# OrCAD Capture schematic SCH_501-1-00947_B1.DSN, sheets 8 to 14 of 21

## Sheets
8 P08_CPU SIGNAL 2: size A2
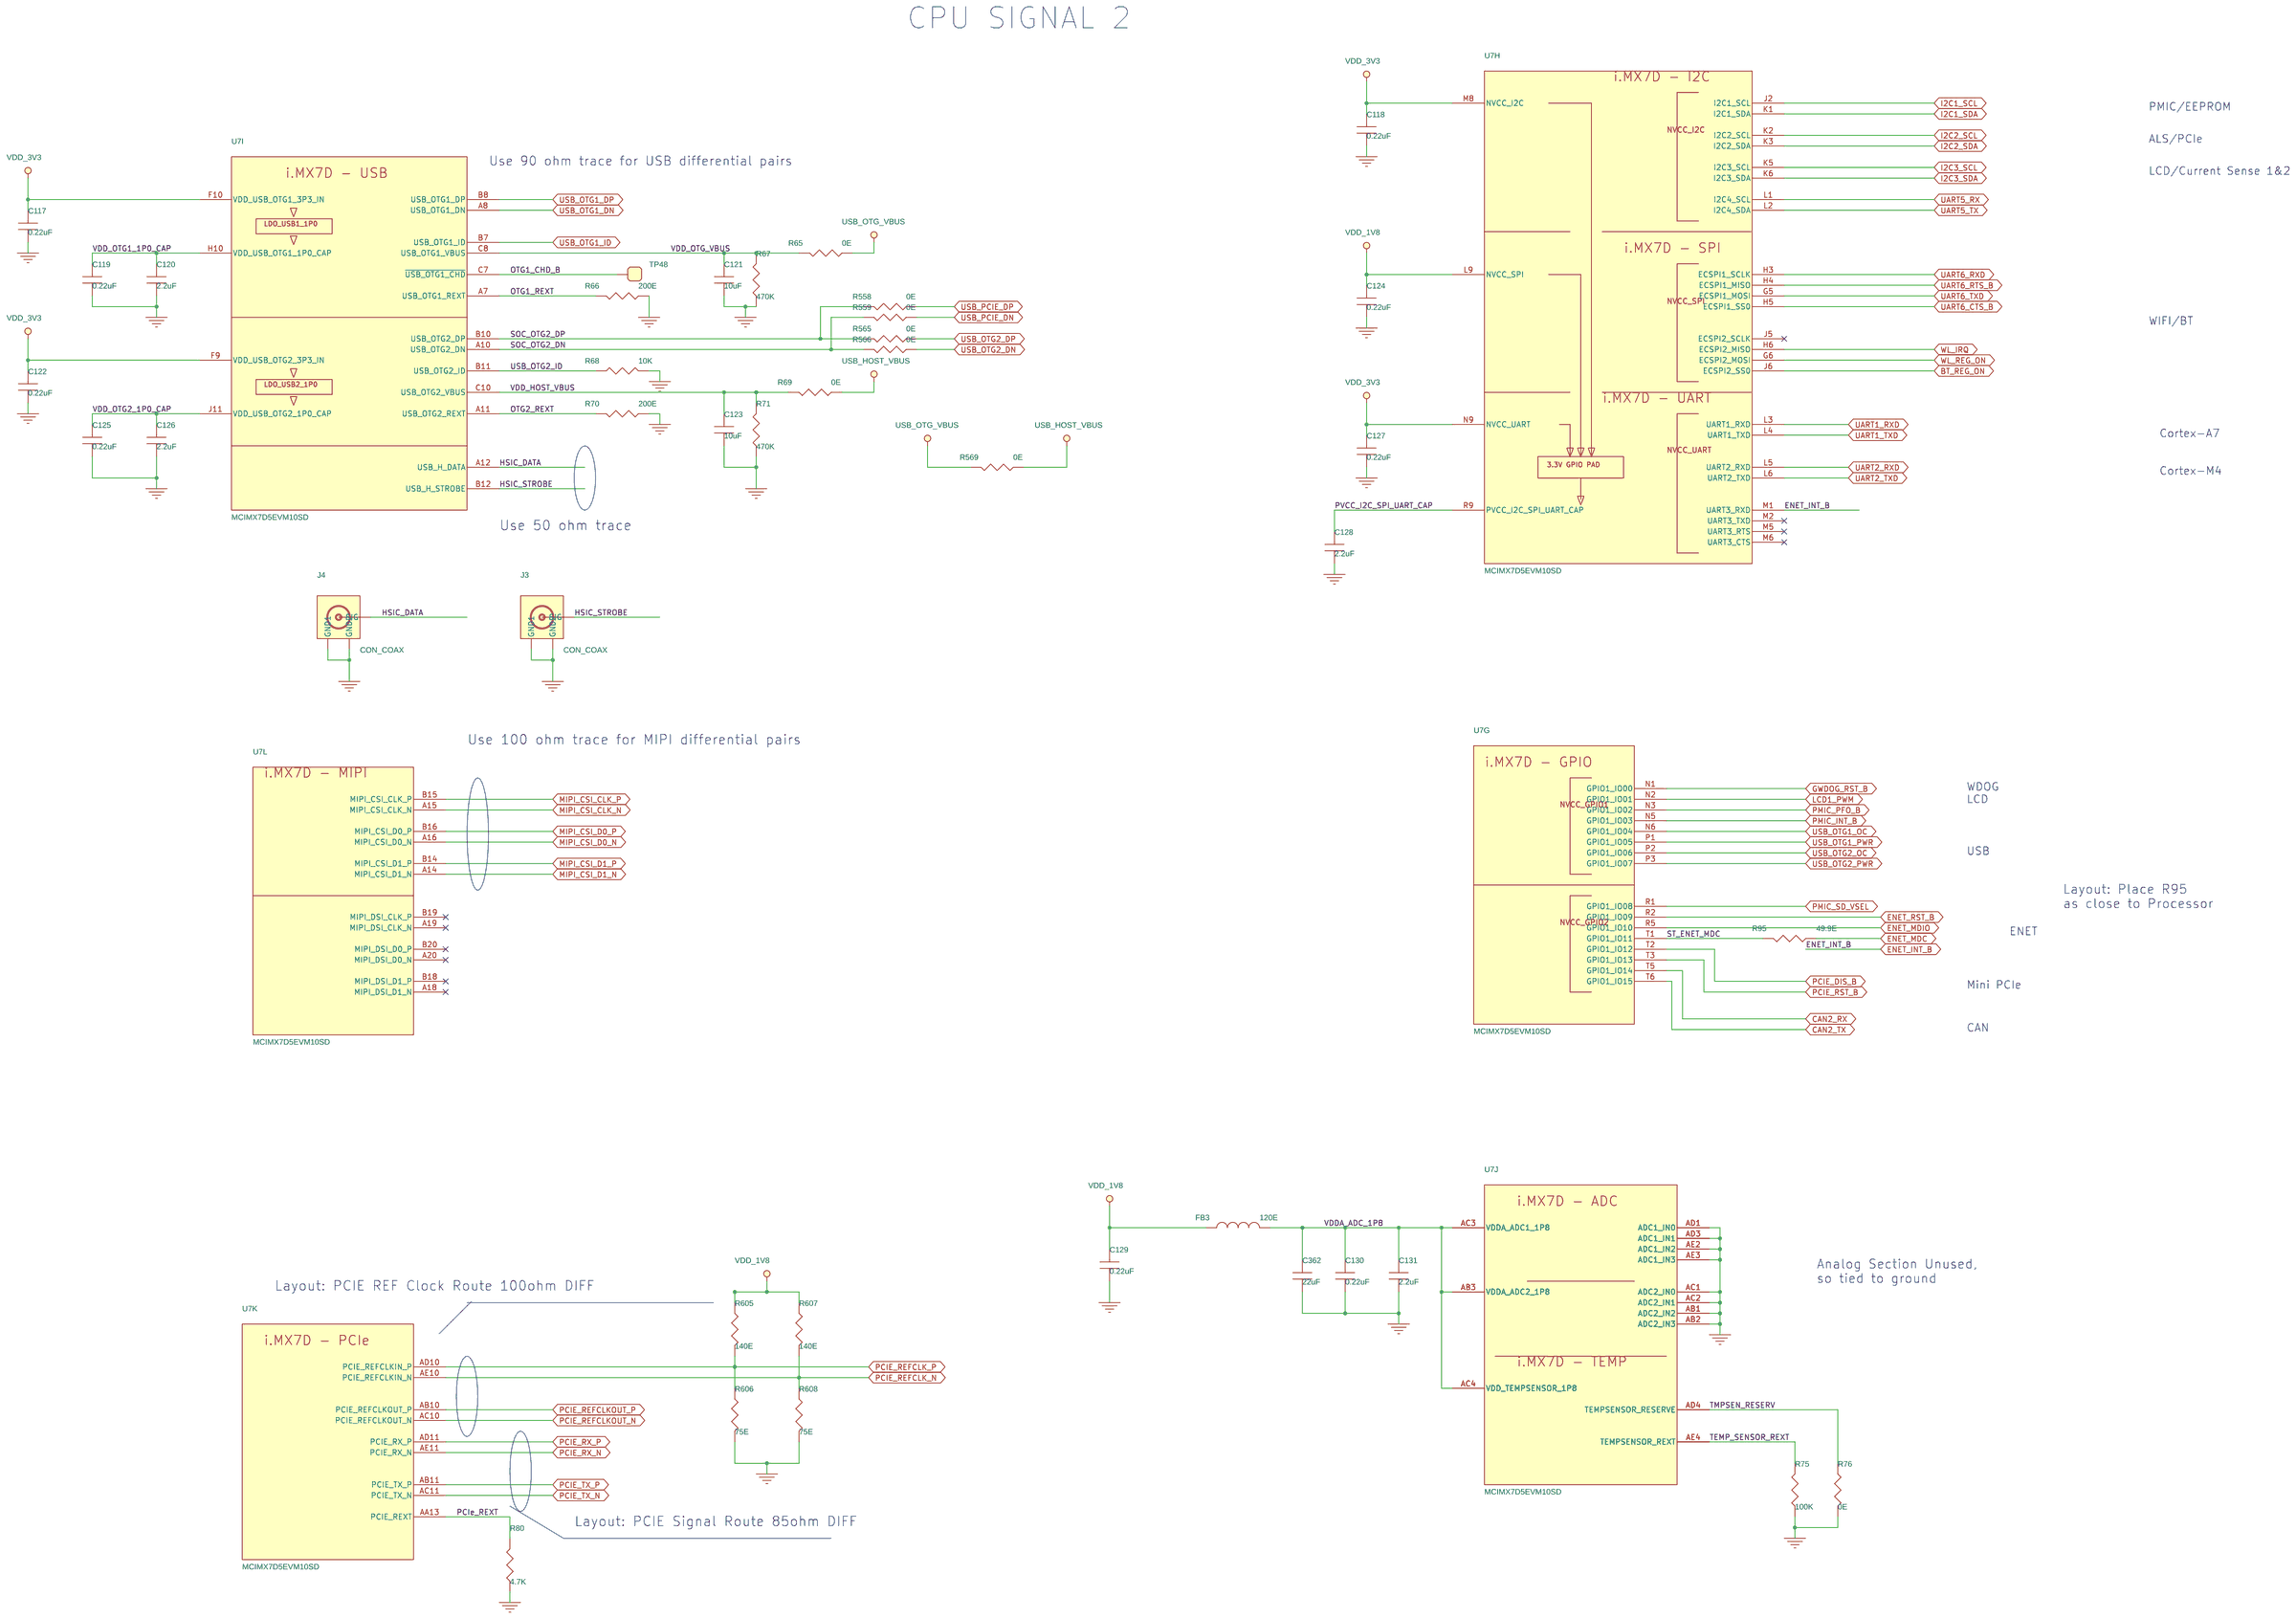
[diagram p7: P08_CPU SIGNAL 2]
9 P09_DDR3L: size A2
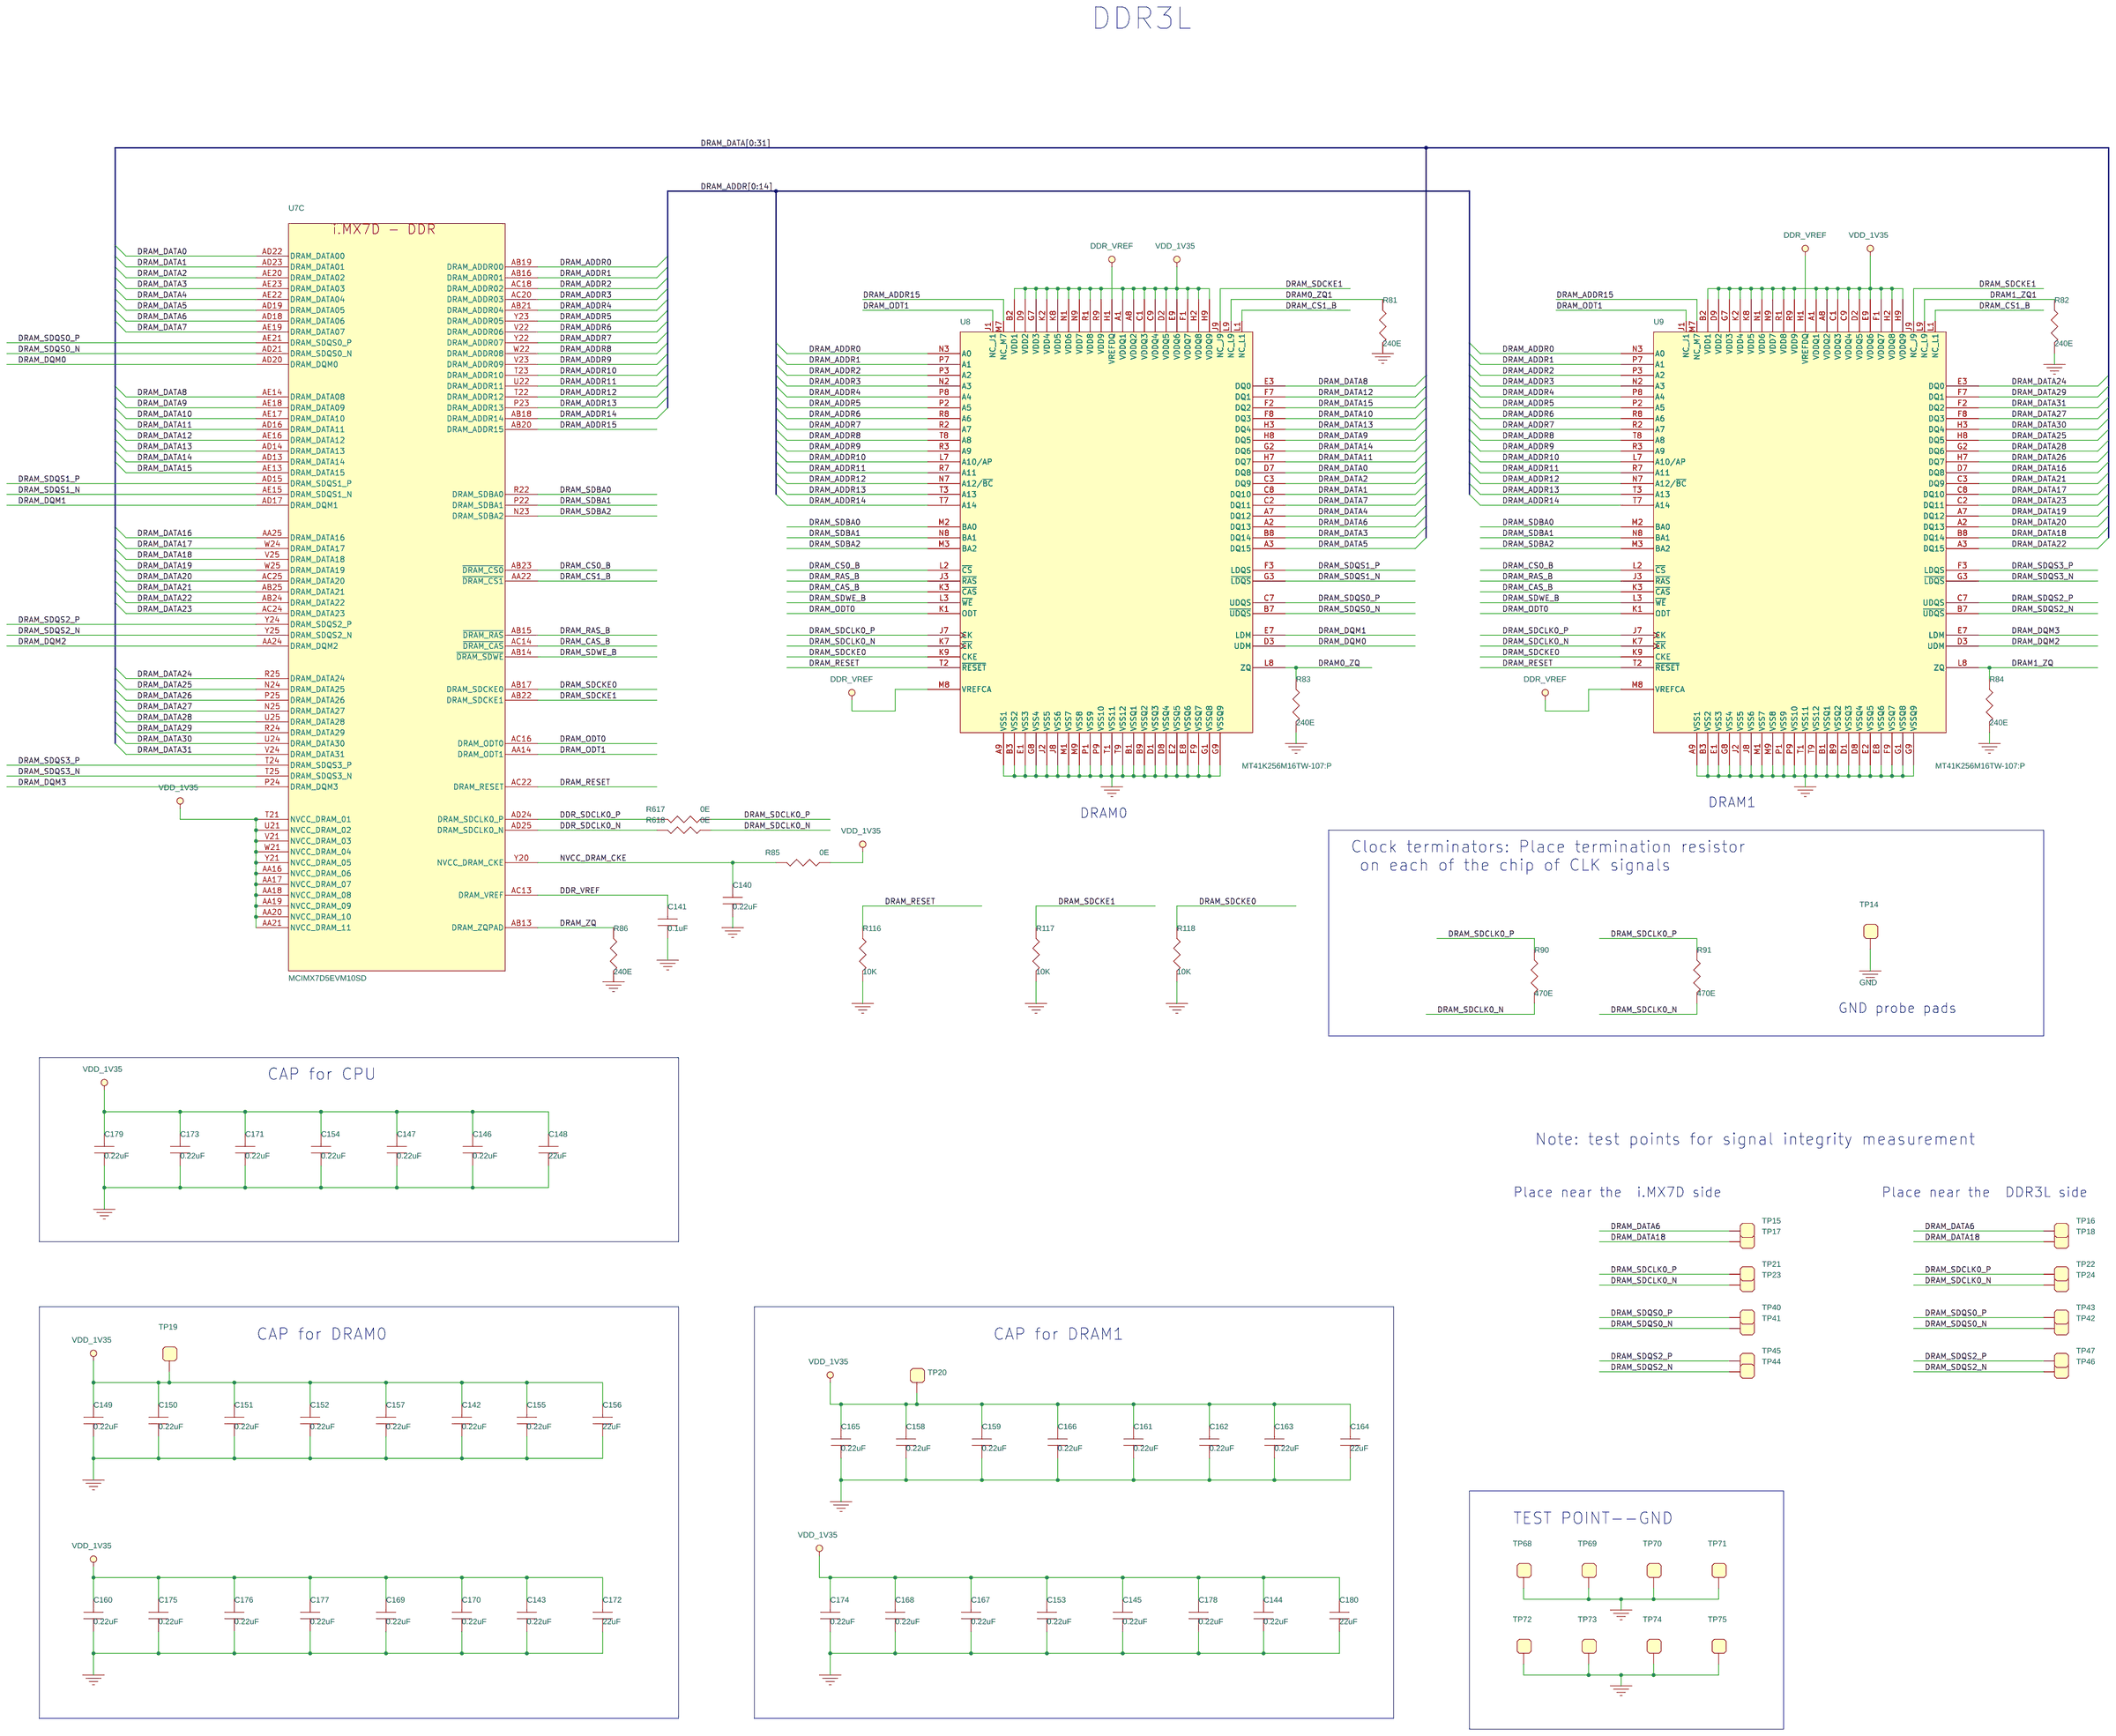
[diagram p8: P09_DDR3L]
10 P11_mini_PCIe: size A2
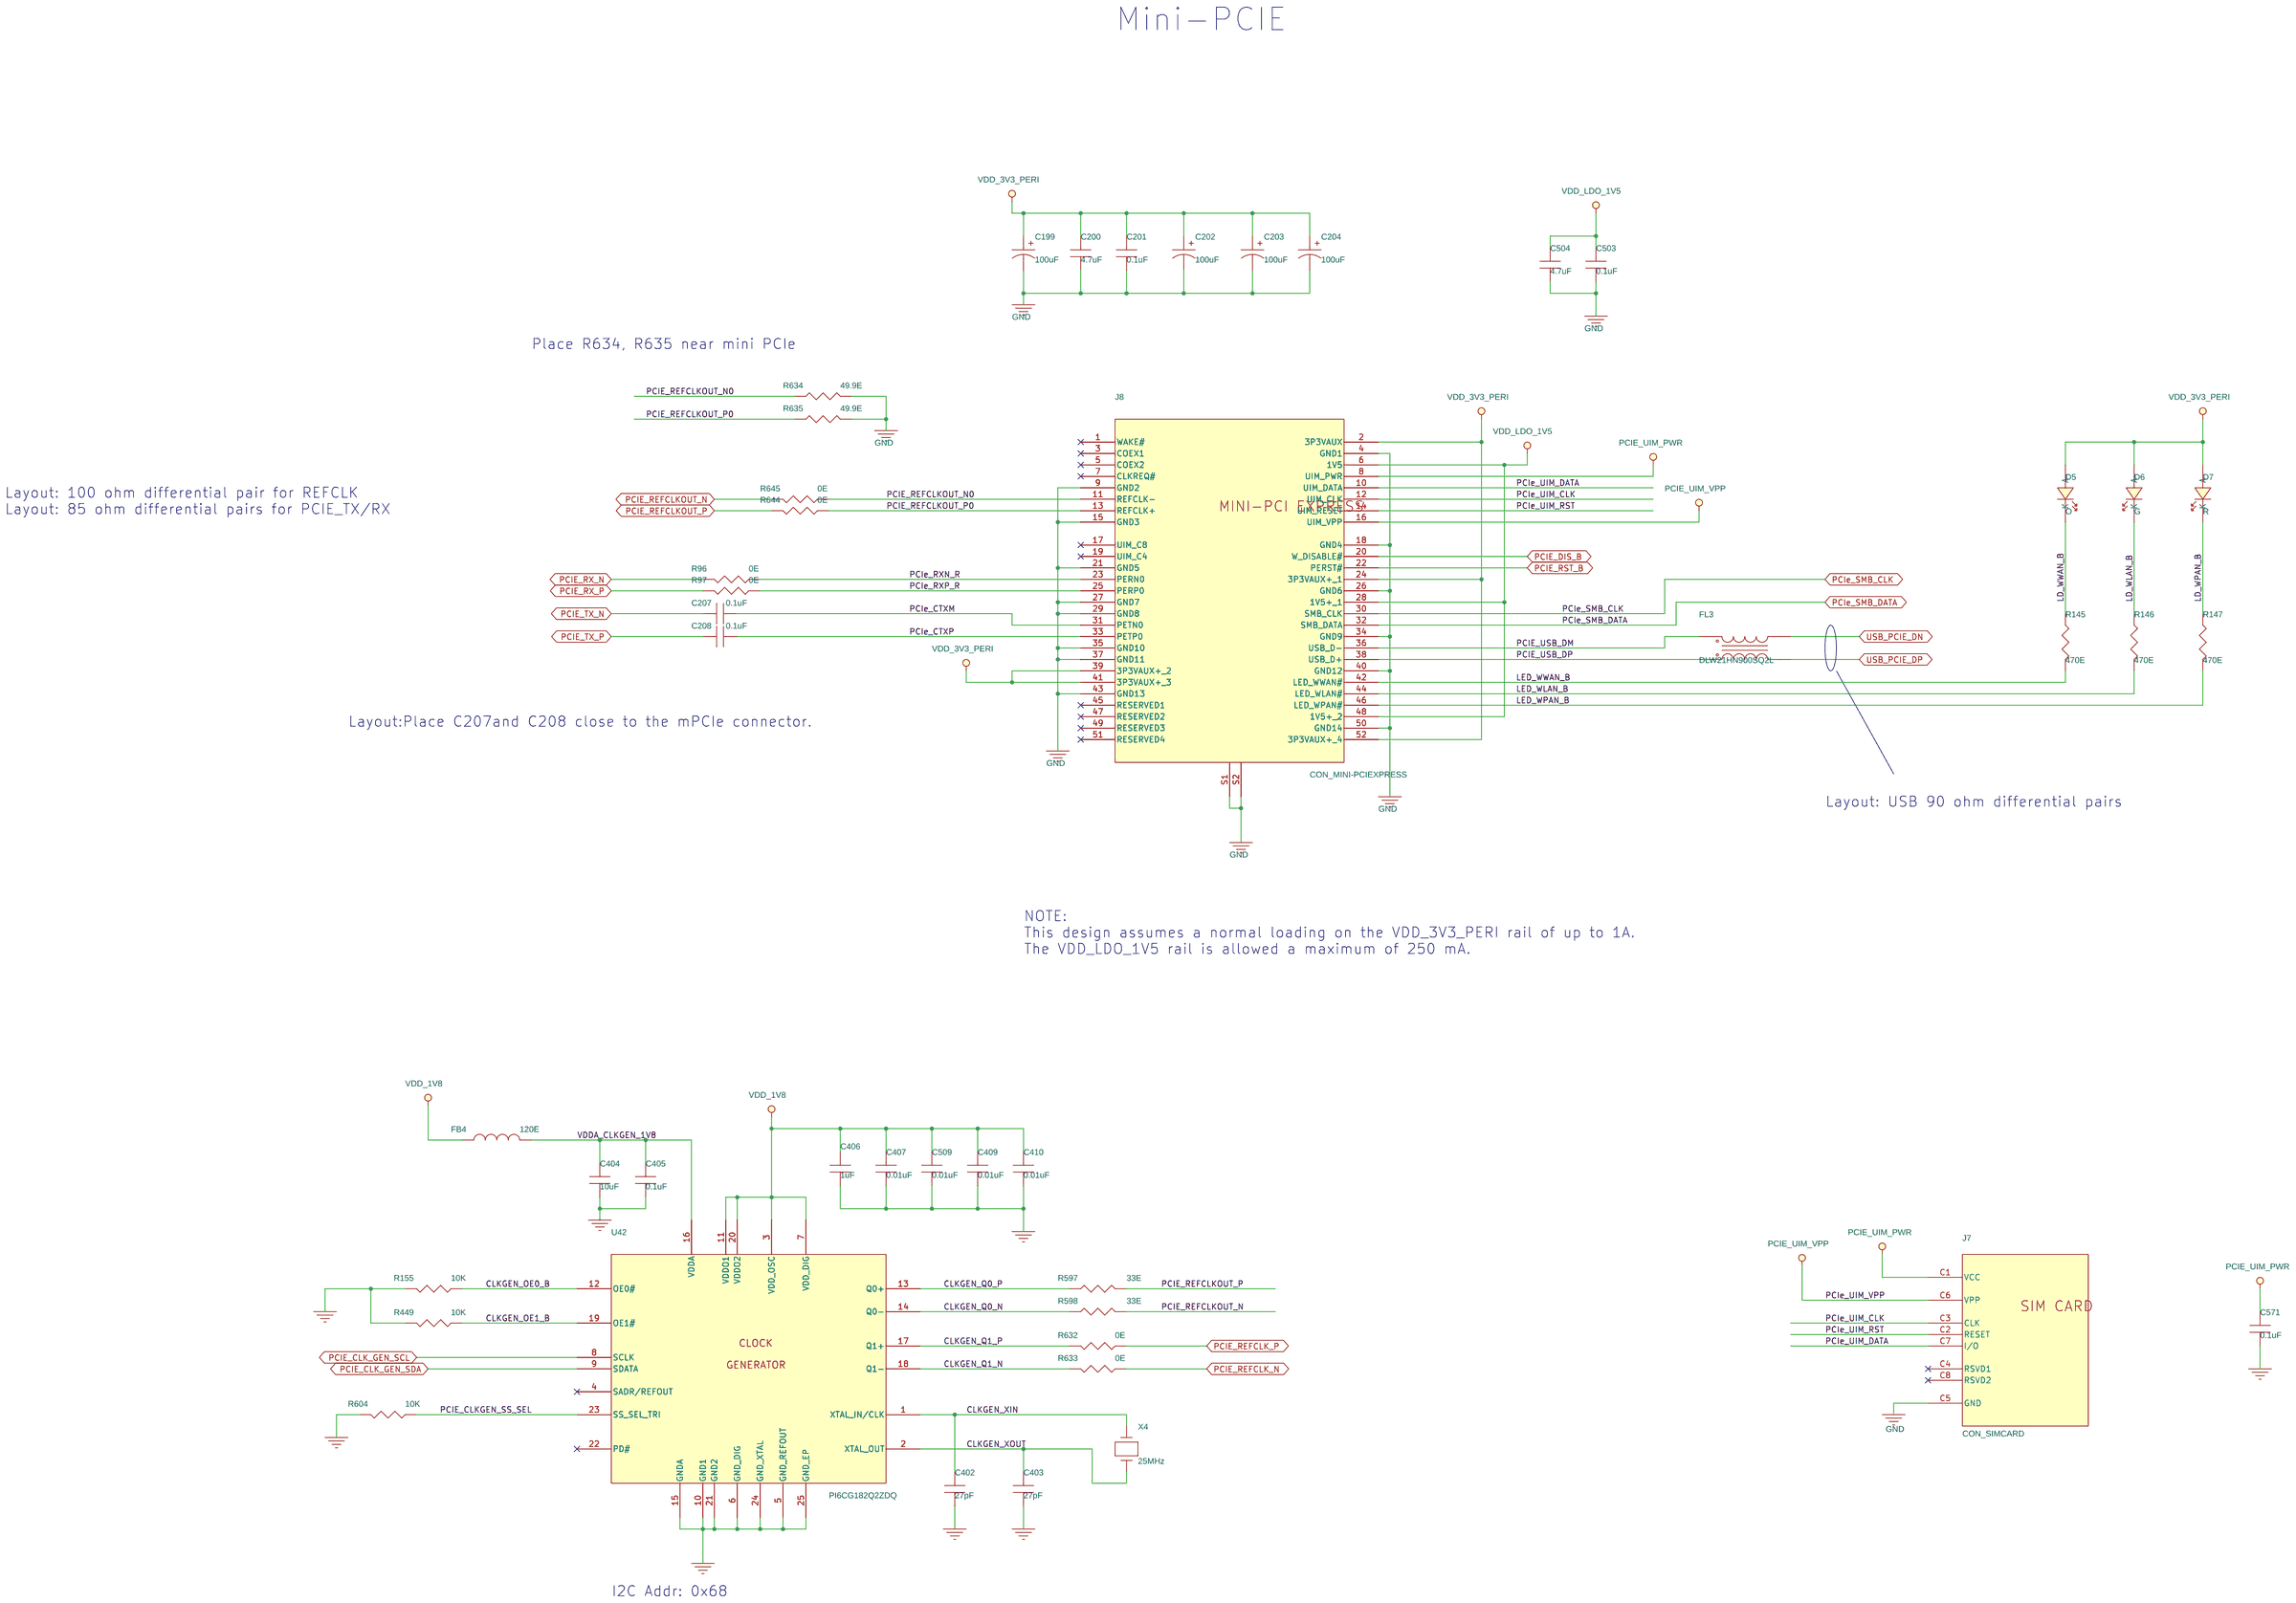
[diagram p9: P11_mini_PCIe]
11 P14_AUDIO: size A2
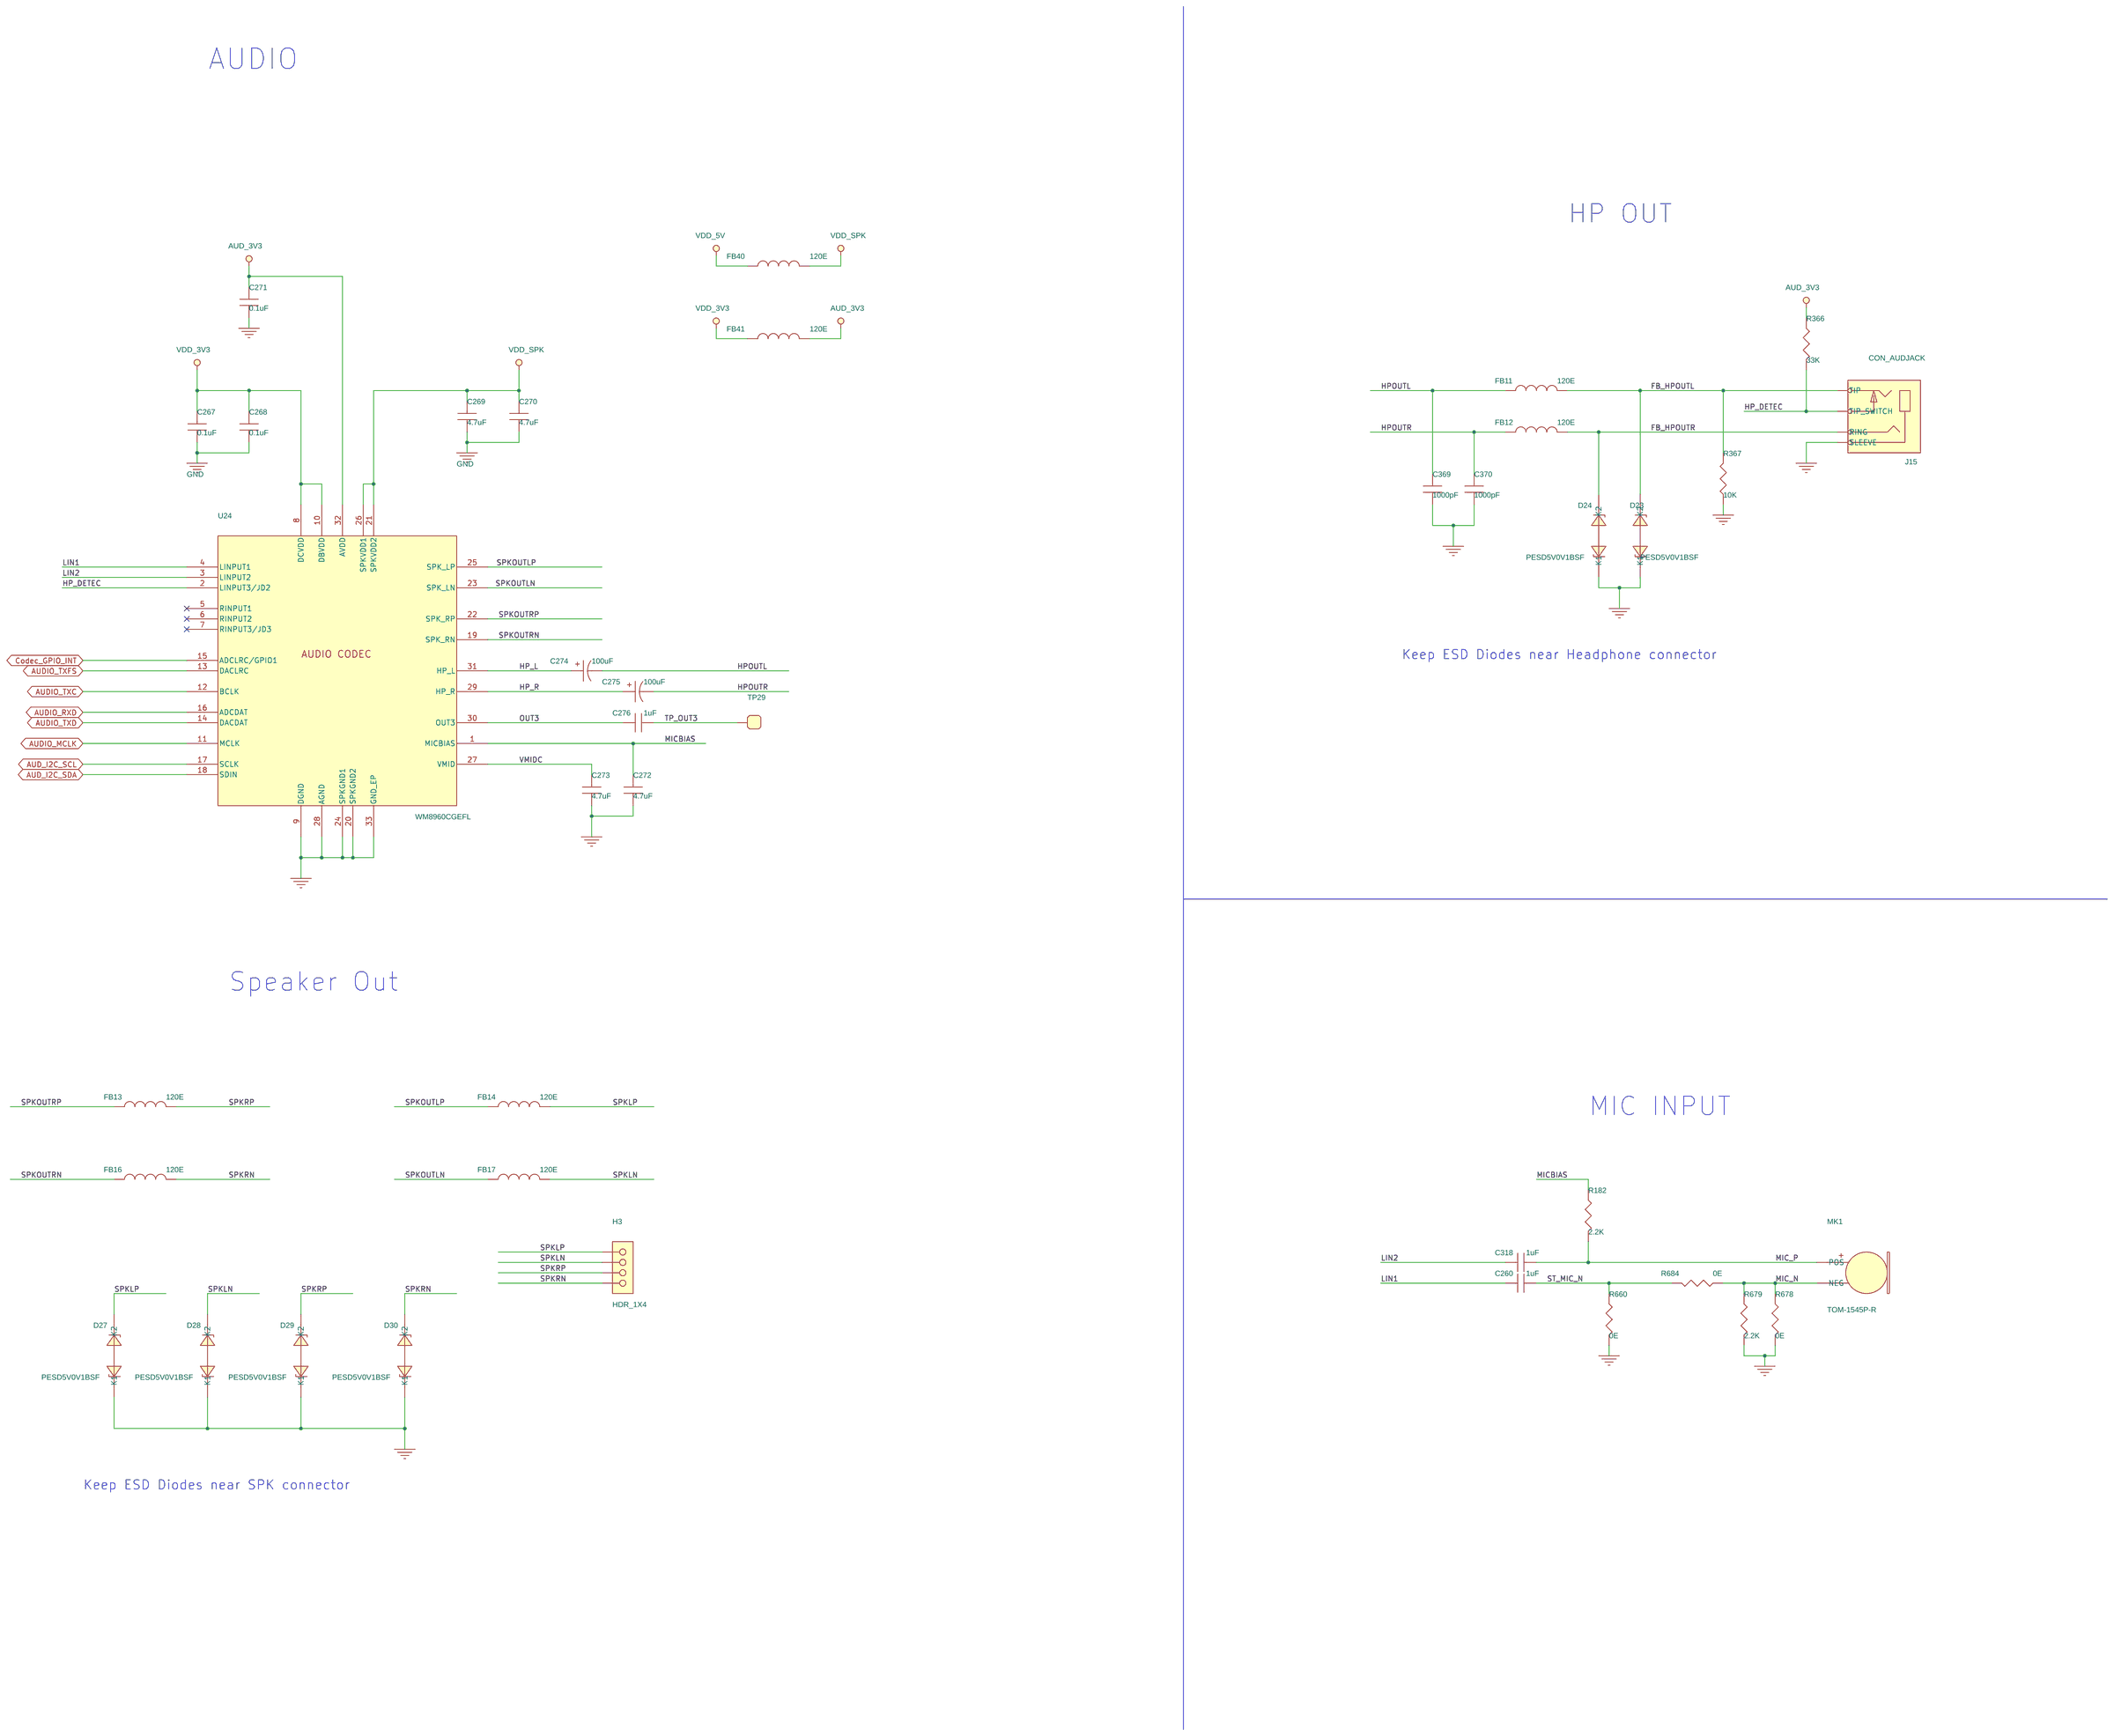
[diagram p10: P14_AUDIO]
12 P17_I2C: size A2
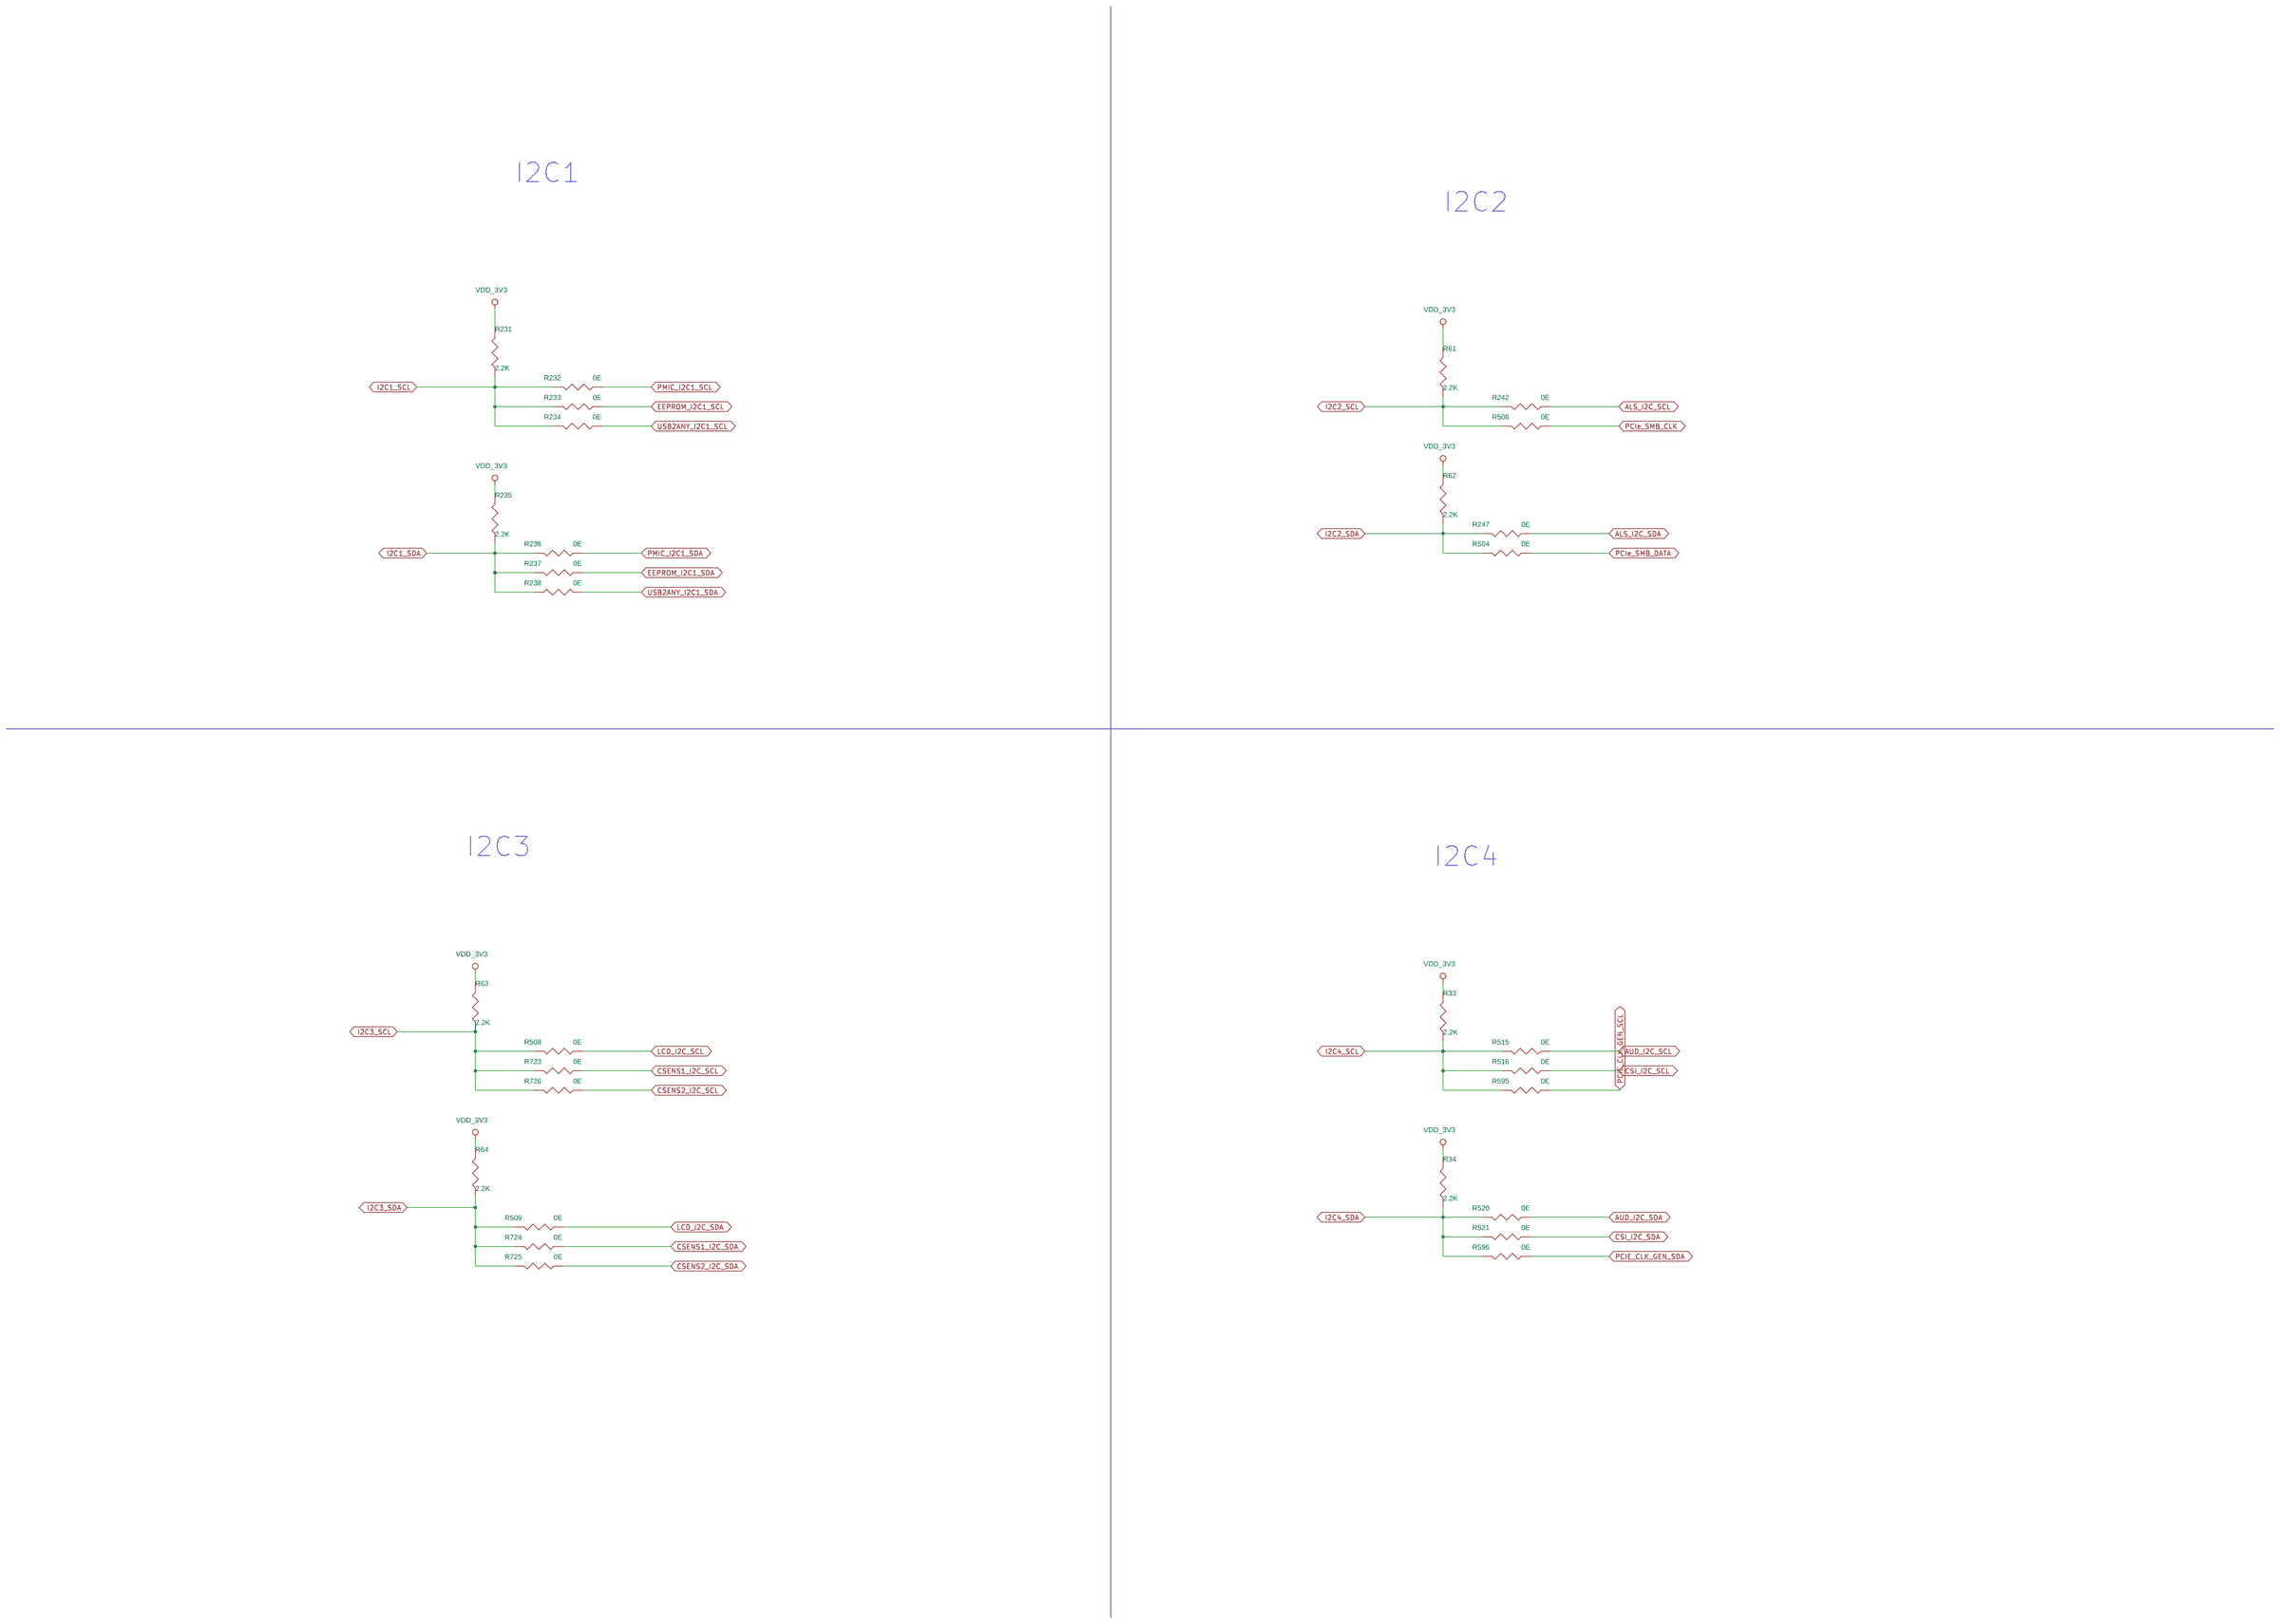
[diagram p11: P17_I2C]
13 P19_ETHERNET: size A2
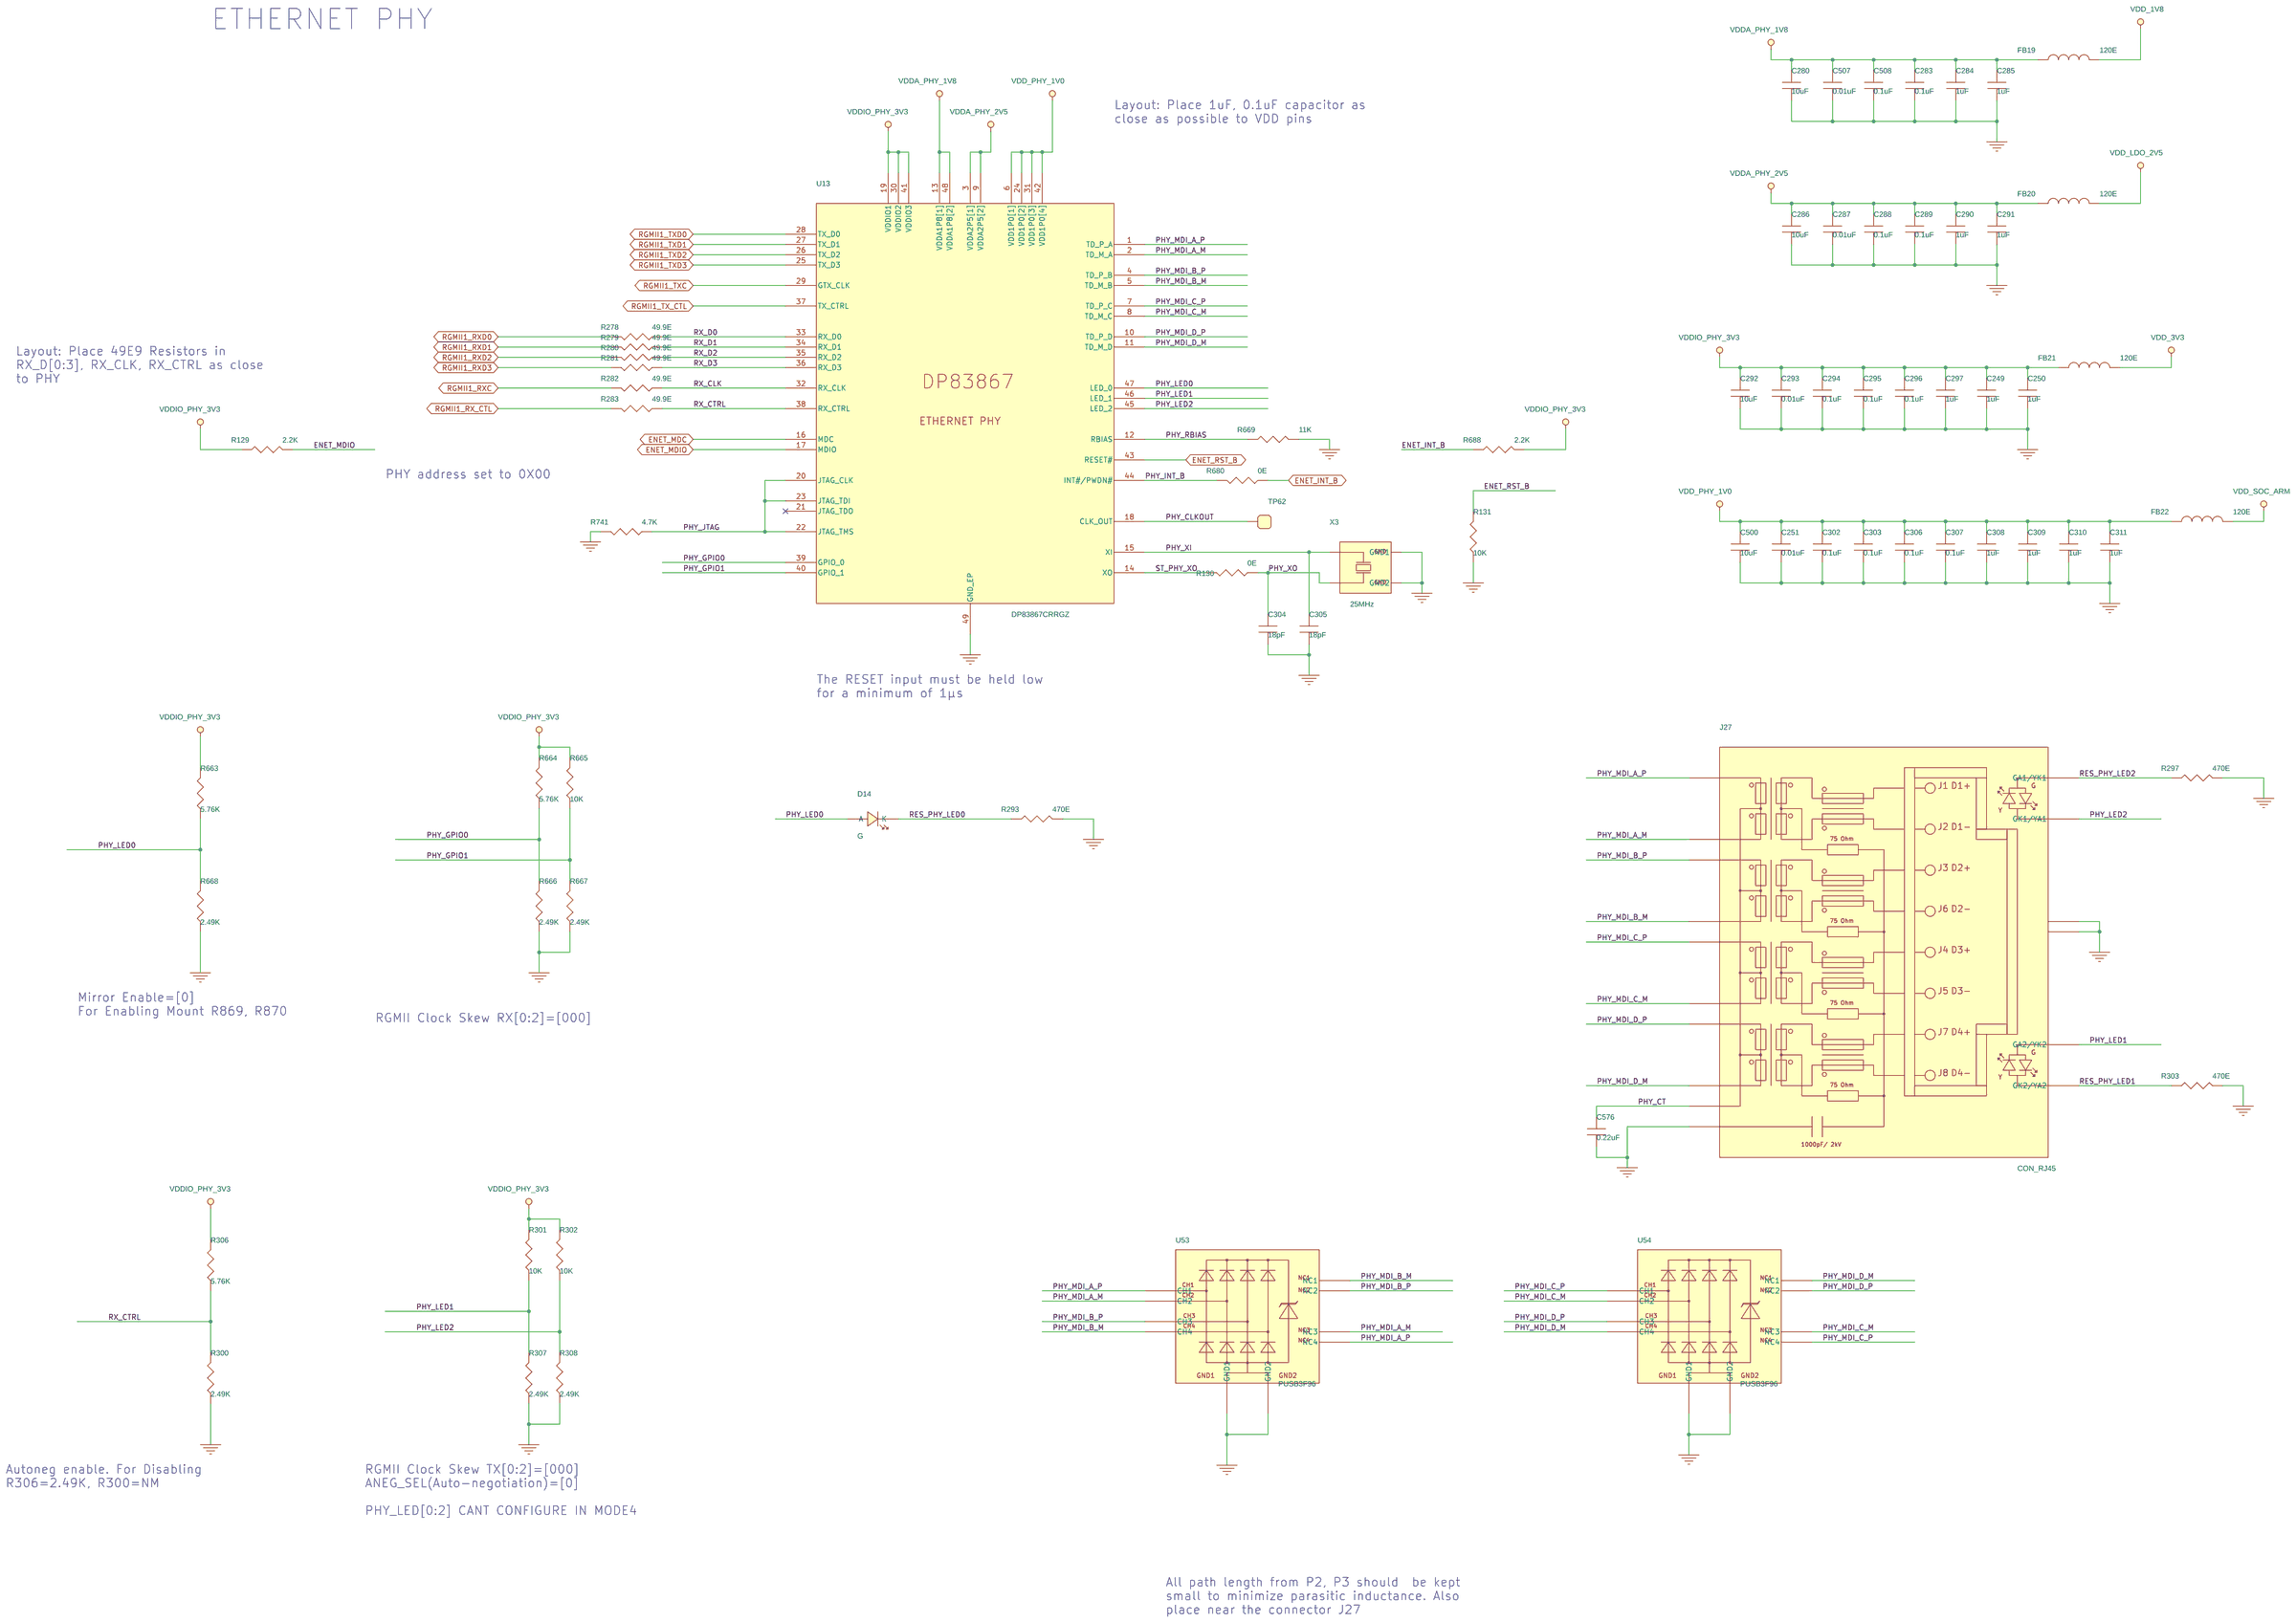
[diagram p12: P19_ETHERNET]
14 P21_MISCELLANEOUS: size A2
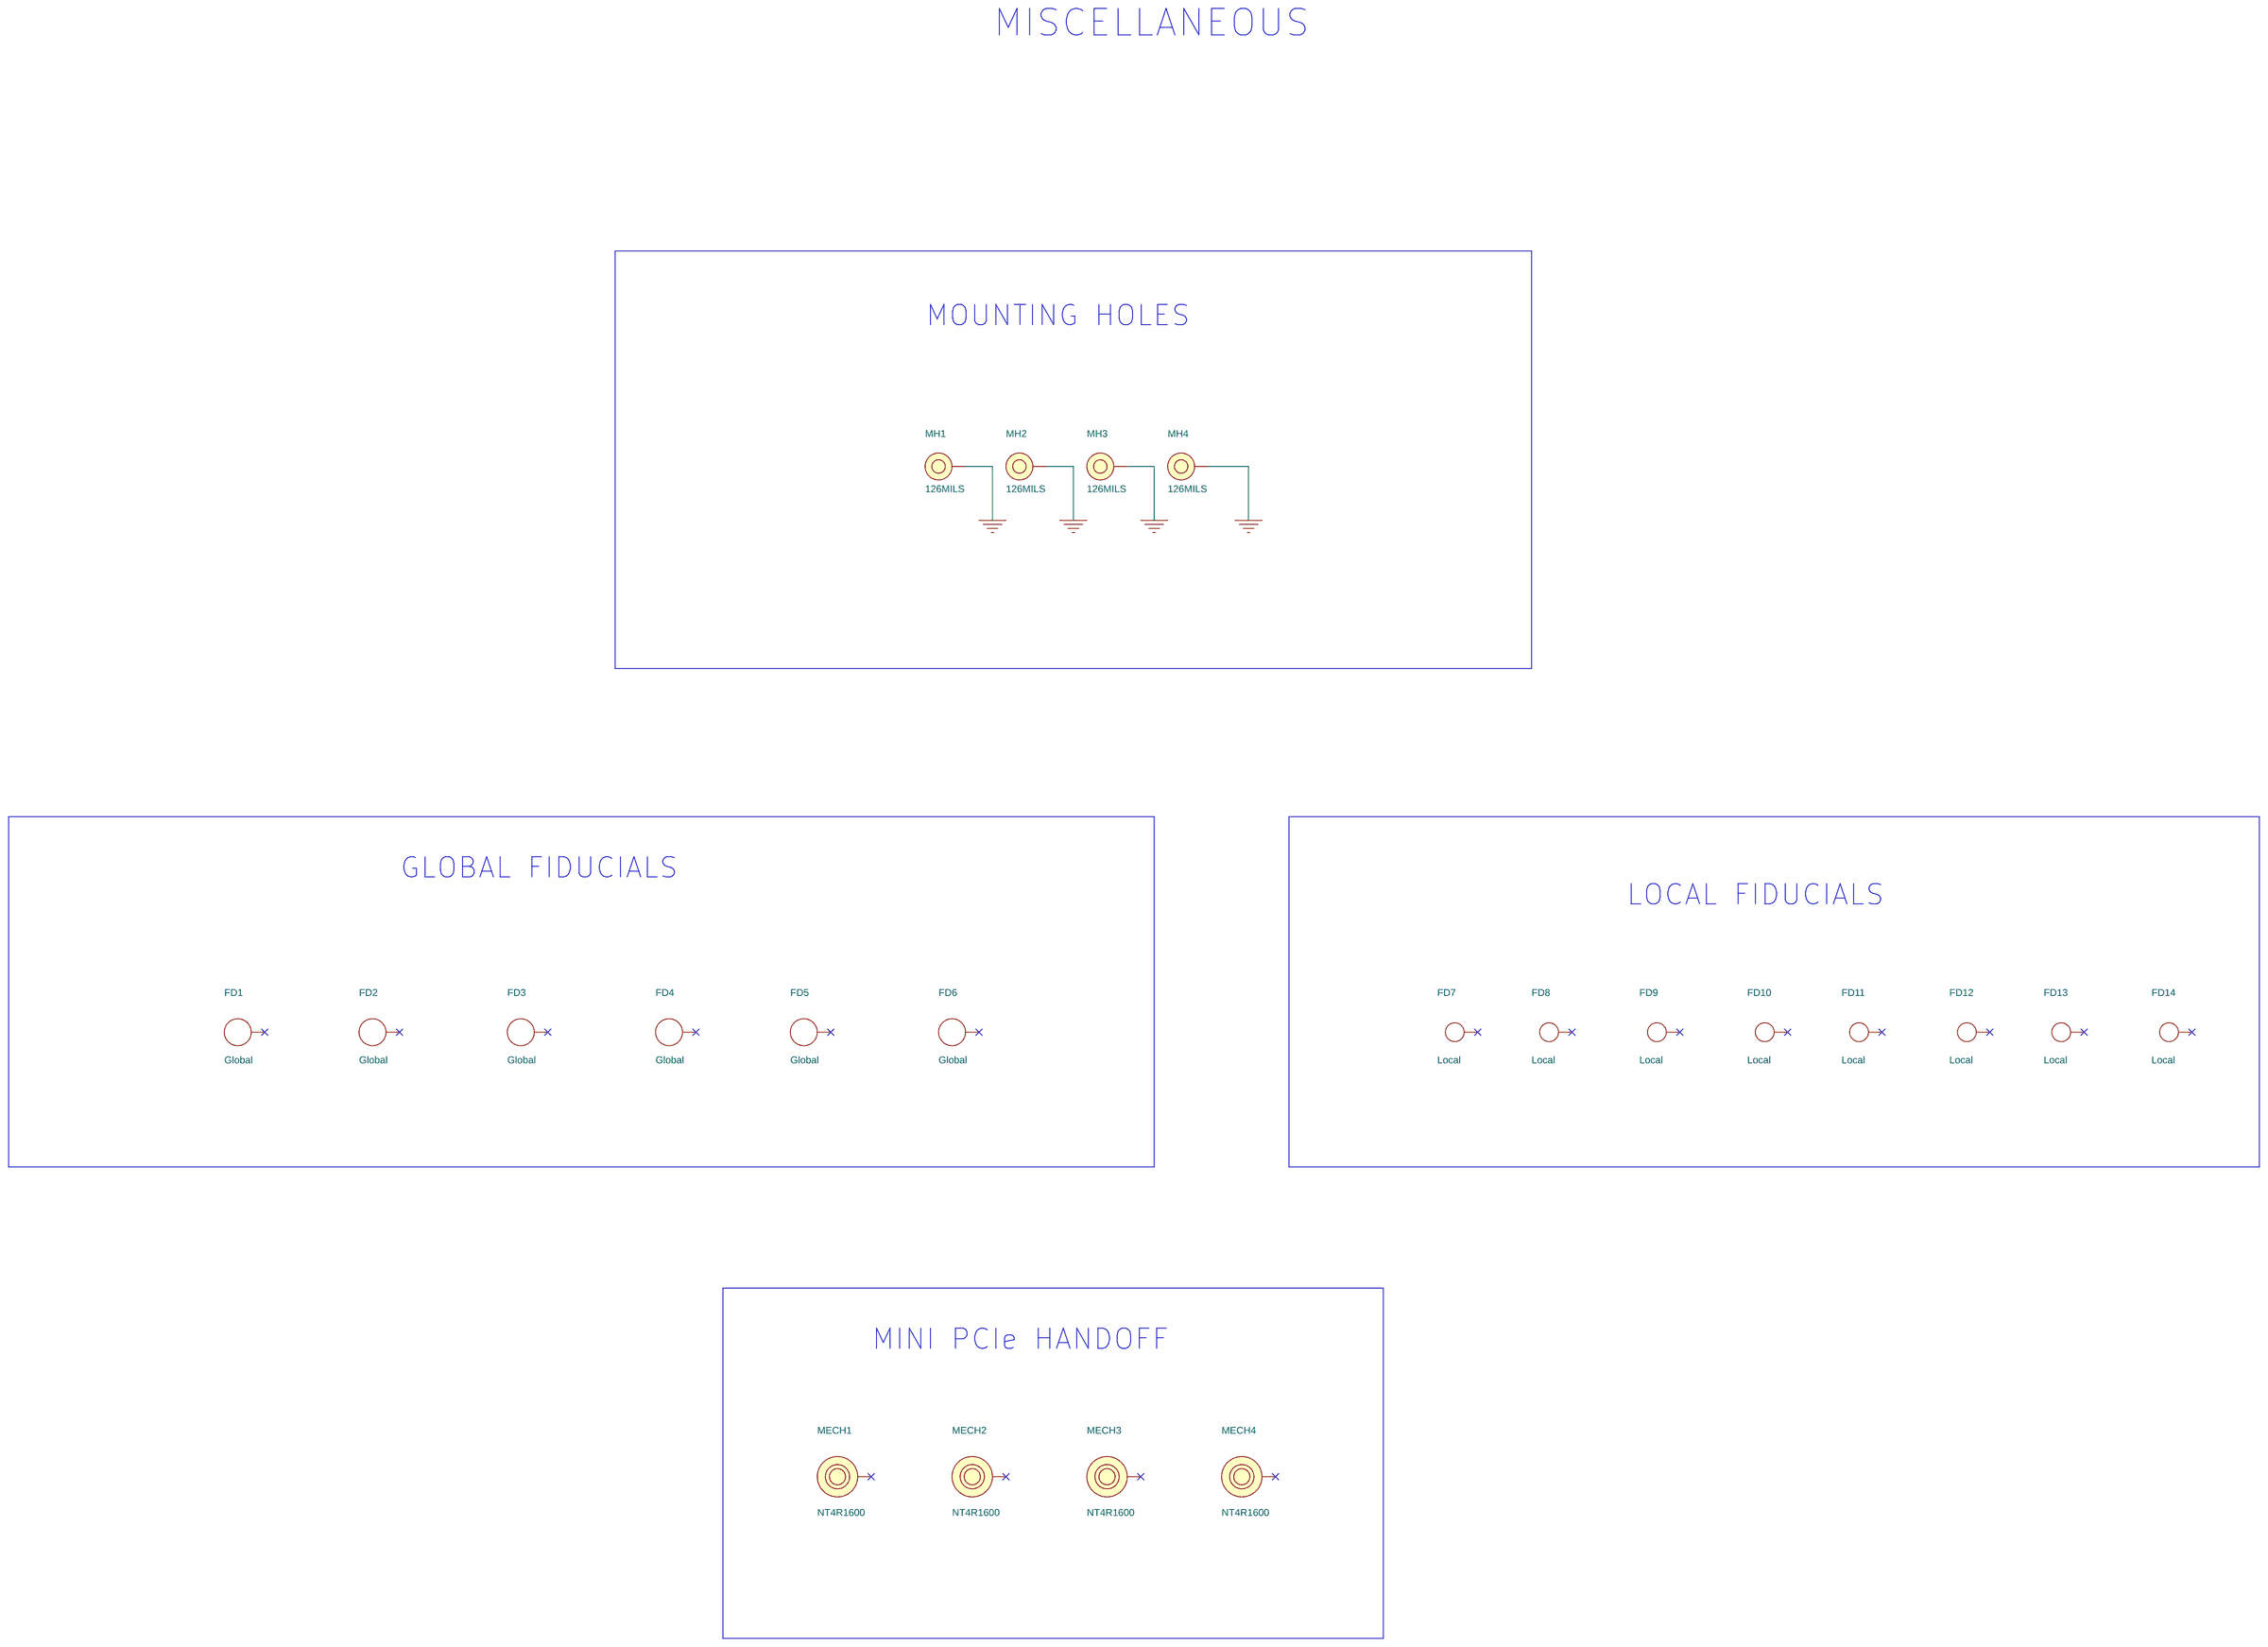
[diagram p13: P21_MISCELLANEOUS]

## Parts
sheet P06_CPU POWER
U7  MCIMX7D5EVM10SD  [bga541x]  (sections A,B,C,D,E,F,G,H,I,J,K,L,M)
sheet P08_CPU SIGNAL 2
C117  0.22uF  [C0402]
C118  0.22uF  [C0402]
C119  0.22uF  [C0402]
C120  2.2uF  [C0402]
C121  10uF  [C0603]
C122  0.22uF  [C0402]
C123  10uF  [C0603]
C124  0.22uF  [C0402]
C125  0.22uF  [C0402]
C126  2.2uF  [C0402]
C127  0.22uF  [C0402]
C128  2.2uF  [C0402]
C129  0.22uF  [C0402]
C130  0.22uF  [C0402]
C131  2.2uF  [C0402]
C362  22uF  [C0603]
FB3  120E  [0402]
J3  CON_COAX  [CON_COAXIAL_3F_1P475_SM_ST]
J4  CON_COAX  [CON_COAXIAL_3F_1P475_SM_ST]
R65  0E  [R0402]
R66  200E  [R0402]
R67  470K  [R0402]
R68  10K  [R0402]
R69  0E  [R0402]
R70  200E  [R0402]
R71  470K  [R0402]
R75  100K  [R0402]
R76  0E  [R0402]
R80  4.7K  [R0402]
R95  49.9E  [R0402]
R558  0E  [R0402]
R559  0E  [R0402]
R565  0E  [R0402]
R566  0E  [R0402]
R569  0E  [R0402]
R605  140E  [R0402]
R606  75E  [R0402]
R607  140E  [R0402]
R608  75E  [R0402]
TP48  SMD  [tp30]
sheet P09_DDR3L
C140  0.22uF  [C0402]
C141  0.1uF  [C0402]
C142  0.22uF  [C0402]
C143  0.22uF  [C0402]
C144  0.22uF  [C0402]
C145  0.22uF  [C0402]
C146  0.22uF  [C0402]
C147  0.22uF  [C0402]
C148  22uF  [C0603]
C149  0.22uF  [C0402]
C150  0.22uF  [C0402]
C151  0.22uF  [C0402]
C152  0.22uF  [C0402]
C153  0.22uF  [C0402]
C154  0.22uF  [C0402]
C155  0.22uF  [C0402]
C156  22uF  [C0603]
C157  0.22uF  [C0402]
C158  0.22uF  [C0402]
C159  0.22uF  [C0402]
C160  0.22uF  [C0402]
C161  0.22uF  [C0402]
C162  0.22uF  [C0402]
C163  0.22uF  [C0402]
C164  22uF  [C0603]
C165  0.22uF  [C0402]
C166  0.22uF  [C0402]
C167  0.22uF  [C0402]
C168  0.22uF  [C0402]
C169  0.22uF  [C0402]
C170  0.22uF  [C0402]
C171  0.22uF  [C0402]
C172  22uF  [C0603]
C173  0.22uF  [C0402]
C174  0.22uF  [C0402]
C175  0.22uF  [C0402]
C176  0.22uF  [C0402]
C177  0.22uF  [C0402]
C178  0.22uF  [C0402]
C179  0.22uF  [C0402]
C180  22uF  [C0603]
R81  240E  [R0402]
R82  240E  [R0402]
R83  240E  [R0402]
R84  240E  [R0402]
R85  0E  [R0402]
R86  240E  [R0402]
R90  470E  [R0402]
R91  470E  [R0402]
R116  10K  [R0402]
R117  10K  [R0402]
R118  10K  [R0402]
R617  0E  [R0402]
R618  0E  [R0402]
TP14  SMD  [tp30]
TP15  SMD  [tp15]
TP16  SMD  [tp15]
TP17  SMD  [tp15]
TP18  SMD  [tp15]
TP19  SMD  [tp30]
TP20  SMD  [tp30]
TP21  SMD  [tp15]
TP22  SMD  [tp15]
TP23  SMD  [tp15]
TP24  SMD  [tp15]
TP40  SMD  [tp15]
TP41  SMD  [tp15]
TP42  SMD  [tp15]
TP43  SMD  [tp15]
TP44  SMD  [tp15]
TP45  SMD  [tp15]
TP46  SMD  [tp15]
TP47  SMD  [tp15]
TP68  SMD  [tp30]
TP69  SMD  [tp30]
TP70  SMD  [tp30]
TP71  SMD  [tp30]
TP72  SMD  [tp30]
TP73  SMD  [tp30]
TP74  SMD  [tp30]
TP75  SMD  [tp30]
U8  MT41K256M16TW-107:P  [bga96_0p8_8p15x14p15]
U9  MT41K256M16TW-107:P  [bga96_0p8_8p15x14p15]
sheet P11_mini_PCIe
C199  100uF  [TCAP_CASEC]
C200  4.7uF  [C0603]
C201  0.1uF  [C0402]
C202  100uF  [TCAP_CASEC]
C203  100uF  [TCAP_CASEC]
C204  100uF  [TCAP_CASEC]
C207  0.1uF  [C0402]
C208  0.1uF  [C0402]
C402  27pF  [0402]
C403  27pF  [0402]
C404  10uF  [C0603]
C405  0.1uF  [C0402]
C406  1uF  [C0603]
C407  0.01uF  [C0402]
C409  0.01uF  [C0402]
C410  0.01uF  [C0402]
C503  0.1uF  [C0402]
C504  4.7uF  [C0603]
C509  0.01uF  [C0402]
C571  0.1uF  [C0402]
D5  O  [LED2_0P9_1X0P6]
D6  G  [LED2_1P5_1P6X0P8_A_A1]
D7  R  [LED2_1P5_1P6X0P8_A_A1]
FB4  120E  [0402]
FL3  DLW21HN900SQ2L  [CM_CHK4_0P8_2X1P2]
J7  CON_SIMCARD  [CON_SIM-CARD_8P_2P54_SM_RA]
J8  CON_MINI-PCIEXPRESS  [CON_PCI_2X26F_0P8_SM_RA_CUST_A1]
R96  0E  [R0402]
R97  0E  [R0402]
R145  470E  [R0402]
R146  470E  [R0402]
R147  470E  [R0402]
R155  10K  [R0402]
R449  10K  [R0402]
R597  33E  [R0402]
R598  33E  [R0402]
R604  10K  [R0402]
R632  0E  [R0402]
R633  0E  [R0402]
R634  49.9E  [R0402]
R635  49.9E  [R0402]
R644  0E  [R0402]
R645  0E  [R0402]
U42  PI6CG182Q2ZDQ  [QFN24_0P5_4X4_EP_R_A1]
X4  25MHz  [XTAL2_3P8_5X3P2]
sheet P14_AUDIO
C260  1uF  [C0603]
C267  0.1uF  [C0402]
C268  0.1uF  [C0402]
C269  4.7uF  [C0603]
C270  4.7uF  [C0603]
C271  0.1uF  [C0402]
C272  4.7uF  [C0603]
C273  4.7uF  [C0603]
C274  100uF  [TCAP_CASEB]
C275  100uF  [TCAP_CASEB]
C276  1uF  [C0603]
C318  1uF  [C0603]
C369  1000pF  [C0402]
C370  1000pF  [C0402]
D23  PESD5V0V1BSF  [DIO-SOD962-2_A1]
D24  PESD5V0V1BSF  [DIO-SOD962-2_A1]
D27  PESD5V0V1BSF  [DIO-SOD962-2_A1]
D28  PESD5V0V1BSF  [DIO-SOD962-2_A1]
D29  PESD5V0V1BSF  [DIO-SOD962-2_A1]
D30  PESD5V0V1BSF  [DIO-SOD962-2_A1]
FB11  120E  [0402]
FB12  120E  [0402]
FB13  120E  [0402]
FB14  120E  [0402]
FB16  120E  [0402]
FB17  120E  [0402]
FB40  120E  [0402]
FB41  120E  [0402]
H3  HDR_1X4  [CON_BERG_1X4M_2P54_SM_ST_A_A1]
J15  CON_AUDJACK  [CON_A-JACK3P5MM_4F_SM_RA]
MK1  TOM-1545P-R  [MIC2_1P2_4P1X4P1_TH]
R182  2.2K  [R0402]
R366  33K  [R0402]
R367  10K  [R0402]
R660  0E  [R0402]
R678  0E  [R0402]
R679  2.2K  [R0402]
R684  0E  [R0402]
TP29  SMD  [tp30]
U24  WM8960CGEFL  [qfn32_1p5h]
sheet P17_I2C
R33  2.2K  [R0402]
R34  2.2K  [R0402]
R61  2.2K  [R0402]
R62  2.2K  [R0402]
R63  2.2K  [R0402]
R64  2.2K  [R0402]
R231  2.2K  [R0402]
R232  0E  [R0402]
R233  0E  [R0402]
R234  0E  [R0402]
R235  2.2K  [R0402]
R236  0E  [R0402]
R237  0E  [R0402]
R238  0E  [R0402]
R242  0E  [R0402]
R247  0E  [R0402]
R504  0E  [R0402]
R506  0E  [R0402]
R508  0E  [R0402]
R509  0E  [R0402]
R515  0E  [0402]
R516  0E  [0402]
R520  0E  [0402]
R521  0E  [0402]
R595  0E  [0402]
R596  0E  [0402]
R723  0E  [R0402]
R724  0E  [R0402]
R725  0E  [R0402]
R726  0E  [R0402]
sheet P19_ETHERNET
C249  1uF  [C0603]
C250  1uF  [C0603]
C251  0.01uF  [C0402]
C280  10uF  [C0603]
C283  0.1uF  [C0402]
C284  1uF  [C0603]
C285  1uF  [C0603]
C286  10uF  [C0603]
C287  0.01uF  [C0402]
C288  0.1uF  [C0402]
C289  0.1uF  [C0402]
C290  1uF  [C0603]
C291  1uF  [C0603]
C292  10uF  [C0603]
C293  0.01uF  [C0402]
C294  0.1uF  [C0402]
C295  0.1uF  [C0402]
C296  0.1uF  [C0402]
C297  1uF  [C0603]
C302  0.1uF  [C0402]
C303  0.1uF  [C0402]
C304  18pF  [C0402]
C305  18pF  [C0402]
C306  0.1uF  [C0402]
C307  0.1uF  [C0402]
C308  1uF  [C0603]
C309  1uF  [C0603]
C310  1uF  [C0603]
C311  1uF  [C0603]
C500  10uF  [C0603]
C507  0.01uF  [C0402]
C508  0.1uF  [C0402]
C576  0.22uF  [C0402]
D14  G  [LED2_1P5_1P6X0P8_A_A1]
FB19  120E  [0402]
FB20  120E  [0402]
FB21  120E  [0402]
FB22  120E  [0402]
J27  CON_RJ45  [CON_RJ45_14F_2P54_TH_RA]
R129  2.2K  [R0402]
R130  0E  [R0402]
R131  10K  [R0402]
R278  49.9E  [R0402]
R279  49.9E  [R0402]
R280  49.9E  [R0402]
R281  49.9E  [R0402]
R282  49.9E  [R0402]
R283  49.9E  [R0402]
R293  470E  [R0402]
R297  470E  [R0402]
R300  2.49K  [R0402]
R301  10K  [R0402]
R302  10K  [R0402]
R303  470E  [R0402]
R306  5.76K  [R0402]
R307  2.49K  [R0402]
R308  2.49K  [R0402]
R663  5.76K  [R0402]
R664  5.76K  [R0402]
R665  10K  [R0402]
R666  2.49K  [R0402]
R667  2.49K  [R0402]
R668  2.49K  [R0402]
R669  11K  [R0402]
R680  0E  [R0402]
R688  2.2K  [R0402]
R741  4.7K  [R0402]
TP62  SMD  [TP40_SMD]
U13  DP83867CRRGZ  [QFN48_0P5_7X7_EP_O_A1]
U53  PUSB3F96  [DFN2510A-10L_0P5_2P5X1]
U54  PUSB3F96  [DFN2510A-10L_0P5_2P5X1]
X3  25MHz  [XTAL4_1P7_3P2X2P5]
sheet P21_MISCELLANEOUS
FD1  Global  [GFD40_120]
FD2  Global  [GFD40_120]
FD3  Global  [GFD40_120]
FD4  Global  [GFD40_120]
FD5  Global  [GFD40_120]
FD6  Global  [GFD40_120]
FD7  Local  [LFD40_80]
FD8  Local  [LFD40_80]
FD9  Local  [LFD40_80]
FD10  Local  [LFD40_80]
FD11  Local  [LFD40_80]
FD12  Local  [LFD40_80]
FD13  Local  [LFD40_80]
FD14  Local  [LFD40_80]
MECH1  NT4R1600  [MECH-M2_RAD4_A1]
MECH2  NT4R1600  [MECH-M2_RAD4_A1]
MECH3  NT4R1600  [MECH-M2_RAD4_A1]
MECH4  NT4R1600  [MECH-M2_RAD4_A1]
MH1  126MILS  [MH236D126T_A1]
MH2  126MILS  [MH236D126T_A1]
MH3  126MILS  [MH236D126T_A1]
MH4  126MILS  [MH236D126T_A1]

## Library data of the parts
U7 = IC_IMX7D_BGA-541P_CUST_A1: IC, uP, IMX7D, Dual Core ARM cortex-A7 Application Processor, 1GHz, MAPBGA-541; EN: 301-1-00396; KEY Number: 301-1-00396@2; Mfg: NXP SEMICONDUCTORS; SPLIT_INST: TRUE; SWAP_INFO: (S1+S2+S3+S4+S5+S6+S7+S8+S9+S10+S11+S12+S13+S14+S15); Temperature: -20°C to +105°C
C117-C119 C122 C124 C125 C127 C129 C130 C140 C142-C147 C149-C155 C157-C163 C165-C171 C173-C179 C576 = CAP_NP: Cap, Cer-X5R, 0.22uF, 10V, 10%, 0402; EN: 102-1-00210; FPLIST: 0402,0402_CIR_A1; KEY Number: 102-1-00210@1; Mfg: MURATA MANUFACTURING CO,LTD; Mfg Part No: GRM155R61A224KE19D; Temperature: -55°C to +85°C
C120 C126 C128 C131 = CAP_NP: Cap, Cer-X5R, 2.2uF, 6.3V, 20%, 0402; EN: 102-1-01843; KEY Number: 102-1-01843@2; Mfg: WALSIN TECHNOLOGY CORP.; Mfg Part No: 0402X225M6R3C*; Temperature: -55°C to +85°C
C121 C123 C280 C286 C292 C404 C500 = CAP_NP: Cap, Cer-X5R, 10uF, 10V, 10%, 0603; EN: 102-1-00156; KEY Number: 102-1-00156@2; Mfg: WALSIN TECHNOLOGY CORP.; Mfg Part No: 0603X106K100CT; Temperature: -55°C to +85°C
C148 C156 C164 C172 C180 C362 = CAP_NP: Cap, Cer-X5R, 22uF, 10V, 20%, 0603; EN: 102-1-01791; KEY Number: 102-1-01791@5; Mfg: MURATA MANUFACTURING CO,LTD; Mfg Part No: GRM188R61A226ME15*; Temperature: -55°C to +85°C
FB3 FB4 FB11-FB14 FB16 FB17 FB19-FB22 FB40 FB41 = FER_BEAD: F-Bead, 120E, 1.3A, SMD0402; EN: 104-1-00007; KEY Number: 104-1-00007@1; Mfg: MURATA MANUFACTURING CO,LTD; Mfg Part No: BLM15PD121SN1B; Temperature: -55°C to +125°C
J3 J4 = CONN_COAX_3P: Conn, Coaxial, Receptacle, 50E, 6GHz, ST, SMD; EN: 201-1-00107; KEY Number: 201-1-00107@1; Mfg: HRS (HIROSE ELECTRIC CO LTD); Mfg Part No: U.FL-R-SMT-1
R65 R69 R76 R85 R96 R97 R130 R232-R234 R236-R238 R242 R247 R504 R506 R508 R509 R515 R516 R520 R521 R558 R559 R565 R566 R569 R595 R596 R617 R618 R632 R633 R644 R645 R660 R678 R680 R684 R723-R726 = RES: Res, Chip, 0E, 1/16W, 1.5A, AEC-Q200, 0402; EN: 101-1-00001; KEY Number: 101-1-00001@2; Mfg: VISHAY; Mfg Part No: CRCW04020000Z0ED; Temperature: -55°C to +155°C
R66 R70 = RES: Res, Chip, 200E, 1/10W, 1%, AEC-Q200, 0402; EN: 101-1-00226; KEY Number: 101-1-00226@2; Mfg: PANASONIC; Mfg Part No: ERJ2RKF2000X; Temperature: -55°C to +155°C
R67 R71 = RES: Res, Chip, 470K, 1/16W, 5%, 0402; EN: 101-1-02833; KEY Number: 101-1-02833@2; Mfg: VISHAY; Mfg Part No: CRCW0402470KJN; Temperature: -55°C to +155°C
R68 R116-R118 R131 R155 R367 R449 R604 = RES: Res, Chip, 10K, 1/16W, 5%, 0402; EN: 101-1-02793; KEY Number: 101-1-02793@2; Mfg: VISHAY; Mfg Part No: CRCW040210K0JNED; Temperature: -55°C to +155°C
R75 = RES: Res, Chip, 100K, 1/16W, 1%, 0402; EN: 101-1-00485; KEY Number: 101-1-00485@3; Mfg: WALSIN TECHNOLOGY CORP.; Mfg Part No: WR04X1003FTL; Temperature: -55°C to +155°C
R80 R741 = RES: Res, Chip, 4.7K, 1/16W, 1%, 0402; EN: 101-1-03446; KEY Number: 101-1-03446@2; Mfg: WALSIN TECHNOLOGY CORP.; Mfg Part No: WR04X4701FTL; Temperature: -55°C to +155°C
R95 R278-R283 R634 R635 = RES: Res, Chip, 49.9E, 1/16W, 1%, 0402; EN: 101-1-00168; KEY Number: 101-1-00168@3; Mfg: WALSIN TECHNOLOGY CORP.; Mfg Part No: WR04X49R9FTL; Temperature: -55°C to +155°C
R605 R607 = RES: Res, Chip, 140E, 1/16W, 1%, 0402; EN: 101-1-00211; KEY Number: 101-1-00211@2; Mfg: VISHAY; Mfg Part No: CRCW0402140RFK; Temperature: -55°C to +155°C
R606 R608 = RES: Res, Chip, 75E, 1/16W, 1%, 0402; EN: 101-1-00185; FPLIST: 0402,0402_HD; KEY Number: 101-1-00185@2; Mfg: VISHAY; Mfg Part No: CRCW040275R0FK**; Temperature: -55°C to +155°C
TP14-TP24 TP29 TP40-TP48 TP62 TP68-TP75 = TEST_POINT_SMD: Testpoint, Pad=1mm, SM=1.3mm, SMD; EN: 666-1-00008; KEY Number: 666-1-00008@1; Mfg: NA; Mfg Part No: 666-1-00008
C141 C207 C208 C283 C288 C289 C294-C296 C302 C303 C306 C307 C503 C508 C571 = CAP_NP: Cap, Cer-X7R, 0.1uF, 16V, 10%, 0402; EN: 102-1-01629; KEY Number: 102-1-01629@4; Mfg: MURATA MANUFACTURING CO,LTD; Mfg Part No: GRM155R71C104KA88*; Temperature: -55°C to +125°C
R81-R84 R86 = RES: Res, Chip, 240E, 1/16W, 1%, 0402; EN: 101-1-03473; KEY Number: 101-1-03473@3; Mfg: WALSIN TECHNOLOGY CORP.; Mfg Part No: WR04X2400FTL; Temperature: -55°C to +155°C
R90 R91 R145-R147 R293 R297 R303 = RES: Res, Chip, 470E, 1/16W, 1%, 100ppm/degC, 0402; EN: 101-1-03571; FPLIST: 0402,0402_HD; KEY Number: 101-1-03571@1; Mfg: VISHAY; Mfg Part No: CRCW0402470RFK; Temperature: -55°C to +155°C
U8 U9 = IC_DDR3-SDRAM_BGA-96P_CUST_A1: IC, DDR3L SDRAM, 512MB, x16bit, 800MHz, FBGA-96; EN: 301-2-00639; KEY Number: 301-2-00639@1; Mfg: MICRON; Temperature: 0°C to +95°C
C199 C202-C204 = CAP_POL: Cap, Tant, 100uF, 10V, 10%, SizeC; EN: 102-2-00060; KEY Number: 102-2-00060@3; Mfg: VISHAY; Mfg Part No: 293D107X9010C; Temperature: -55°C to +125°C
C200 C269 C270 C272 C273 C504 = CAP_NP: Cap, Cer-X5R, 4.7uF, 10V, 10%, 0603; EN: 102-1-01650; KEY Number: 102-1-01650@2; Mfg: WALSIN TECHNOLOGY CORP.; Mfg Part No: 0603X475K100CT; Temperature: -55°C to +85°C
C201 C267 C268 C271 C405 = CAP_NP: Cap, Cer-X7R, 0.1uF, 16V, 10%, 0402; EN: 102-1-01629; KEY Number: 102-1-01629@4; Mfg: MURATA MANUFACTURING CO,LTD; Mfg Part No: GRM155R71C104KA88D; Temperature: -55°C to +125°C
C402 C403 = CAP_NP: Cap, Cer-NPO, 27pF, 25V, 1%, 0402; EN: 102-1-00745; KEY Number: 102-1-00745@1; Mfg: AVX CORPORATION; Mfg Part No: 04023A270FAT2A; Temperature: -55°C to +125°C
C249 C250 C260 C276 C284 C285 C290 C291 C297 C308-C311 C318 C406 = CAP_NP: Cap, Cer-X7R, 1uF, 10V, 10%, 0603; EN: 102-1-00097; FPLIST: 0603,0603_HD; KEY Number: 102-1-00097@1; Mfg: AVX CORPORATION; Mfg Part No: 0603ZC105KAT2A; Temperature: -55°C to +125°C
C251 C287 C293 C407 C409 C410 C507 C509 = CAP_NP: Cap, Cer-X7R, 0.01uF, 10V, 10%, 0402; EN: 102-1-00001; KEY Number: 102-1-00001@1; Mfg: AVX CORPORATION; Mfg Part No: 0402ZC103KAT2A; Temperature: -55°C to +125°C
D5 = DIODE_LED_A: LED, Single, Orange, SMD; EN: 106-4-00084; KEY Number: 106-4-00084@1; Mfg: ROHM; Mfg Part No: SML-P12DTT86; Temperature: -40°C to +85°C
D6 D14 = DIODE_LED: LED, Single, Green, SMD; EN: 106-4-00248; KEY Number: 106-4-00248@1; Mfg: LITE-ON; Mfg Part No: LTST-C193KGKT-5A; Temperature: -55°C to +85°C
D7 = DIODE_LED: LED, Single, RED, SMD; EN: 106-4-00247; KEY Number: 106-4-00247@1; Mfg: LITE-ON; Mfg Part No: LTST-C193KRKT-5A; Temperature: -30°C to +85°C
FL3 = FIL_COM-MODE_4P_C_POL: Filter, Choke coil, CM, 90E, 330mA, Signal Line, SMD; EN: 303-0-00024; KEY Number: 303-0-00024@1; Mfg: MURATA MANUFACTURING CO,LTD; Temperature: -40°C to +85°C
J7 = CONN_SIMCARD_8P: Conn, SIM Card, 1x1, Push In-Pull Out, RA, SMD; EN: 201-2-00086; KEY Number: 201-2-00086@1; Mfg: C&K COMPONENTS; Mfg Part No: CCM03-3504LFT
J8 = CONN_MINI-PCIEXPRESS-52_54P_A: Conn, Mini PCI Express, 2x26, 0.8mm, RA, SMD; EN: 201-2-00647; KEY Number: 201-2-00647@1; Mfg: JAE (JAPAN AVIATION ELECTRONICS INDUSTRY, LTD); Mfg Part No: MM60-52B1-E1-****; Temperature: -40°C to +85°C
R597 R598 = RES: Res, Chip, 33E, 1/16W, 1%, 0402; EN: 101-1-03680; KEY Number: 101-1-03680@2; Mfg: WALSIN TECHNOLOGY CORP.; Mfg Part No: WR04X33R0FTL; Temperature: -55°C to +155°C
U42 = IC_CLOCK-GENERATOR_24P_EP_C_A1: IC, PI6CG182Q2, PCIe Clock Generator, 2 Output, 100MHz, AEC-Q100, TQFN-24; EN: 301-0-02438; KEY Number: 301-0-02438@1; Mfg: DIODES INCORPORATED; Mfg Part No: PI6CG182Q2ZDQEX; Temperature: -40°C to +105°C
X4 = CRYSTAL: XTAL, 25MHz, 18pF, +/-20ppm, 40E, 3.2x5mm, SMD; EN: 108-1-00038; KEY Number: 108-1-00038@1; Mfg: CTS; Mfg Part No: 445I23D25M00000; Temperature: -40°C to +85°C
C274 C275 = CAP_POL: Cap, Tant, 100uF, 10V, 20%, SizeB; EN: 102-2-00272; KEY Number: 102-2-00272@1; Mfg: AVX CORPORATION; Mfg Part No: TAJB107M010RNJ
C369 C370 = CAP_NP: Cap, Cer-X7R, 1000pF, 50V, 10%, 0402; EN: 102-1-00054; KEY Number: 102-1-00054@3; Mfg: WALSIN TECHNOLOGY CORP.; Mfg Part No: 0402B102K500CT; Temperature: -55°C to +125°C
D23 D24 D27-D30 = DIODE_TVS_BIDIR_C_A1: Diode, ESD-Bidir, 5V, 8W, SOD962-2; EN: 305-1-00289; KEY Number: 305-1-00289@2; Mfg: NEXPERIA; Temperature: -55°C to +150°C
H3 = HDR_1X4_4P: Conn, Berg strip, 1x4, 2.54mm, 3A, ST, SMD; EN: 201-1-00701; KEY Number: 201-1-00701@1; Mfg: MOLEX; Mfg Part No: 87898-0424; Temperature: -55°C to +105°C
J15 = CONN_AUDJACK_4P: Conn, Audio Jack Stereo, 1A, 3.5mm ID, 3-Contact, Tip Switch, RA, SMD; EN: 201-2-00130; KEY Number: 201-2-00130@1; Mfg: CUI INC; Mfg Part No: SJ-3524-SMT
MK1 = MICROPHONE: MIC, Condensor, -45dB, 2.2K, OMNI; EN: 401-1-00015; KEY Number: 401-1-00015@1; Mfg: PUI AUDIO INC.
R33 R34 R61-R64 R129 R182 R231 R235 R679 R688 = RES: Res, Chip, 2.2K, 1/16W, 5%, 0402; EN: 101-1-02777; KEY Number: 101-1-02777@2; Mfg: VISHAY; Mfg Part No: CRCW04022K20JN**; Temperature: -55°C to +155°C
R366 = RES: Res, Chip, 33K, 1/16W, 5%, 0402; EN: 101-1-02805; KEY Number: 101-1-02805@2; Mfg: VISHAY; Mfg Part No: CRCW040233K0JN**; Temperature: -55°C to +155°C
U24 = IC_AUDIO-CODEC_32P_EP_A_A1: IC, WM8960, Stereo Audio Codec, Class D, 1W, QFN-32; EN: 301-0-01482; KEY Number: 301-0-01482@1; Mfg: WOLFSON MICROELECTRONICS PLC; Mfg Part No: WM8960CGEFL/*; Temperature: -40°C to +85°C
C304 C305 = CAP_NP: Cap, Cer-NPO, 18pF, 50V, 5%, 0402; EN: 102-1-01806; KEY Number: 102-1-01806@1; Mfg: MURATA MANUFACTURING CO,LTD; Mfg Part No: GRM1555C1H180JA01D; Temperature: -55°C to +125°C
J27 = CONN_RJ45-14X1_16P_A: Conn, RJ45 Jack with Magnetics, Shielded, LED(G/Y, G/Y), RA, TH; EN: 201-2-00061; KEY Number: 201-2-00061@1; Mfg: WURTH ELECTRONIK, INC; Mfg Part No: 7499111446; Temperature: -40°C to +85°C
R300 R307 R308 R666-R668 = RES: Res, Chip, 2.49K, 1/16W, 1%, 0402; EN: 101-1-00331; KEY Number: 101-1-00331@3; Mfg: WALSIN TECHNOLOGY CORP.; Mfg Part No: WR04X2491FTL; Temperature: -55°C to +155°C
R301 R302 R665 = RES: Res, Chip, 10K, 1/16W, 1%, 0402; EN: 101-1-04184; KEY Number: 101-1-04184@1; Mfg: WALSIN TECHNOLOGY CORP.; Mfg Part No: WR04X1002FTL; Temperature: -55°C to +155°C
R306 R663 R664 = RES: Res, Chip, 5.76K, 1/16W, 1%, 0402; EN: 101-1-00366; KEY Number: 101-1-00366@2; Mfg: VISHAY; Mfg Part No: CRCW04025K76FK; Temperature: -55°C to +155°C
R669 = RES: Res, Chip, 11K, 1/16W, 1%, 0402; EN: 101-1-00393; KEY Number: 101-1-00393@2; Mfg: VISHAY; Mfg Part No: CRCW040211K0FK; Temperature: -55°C to +155°C
U13 = IC_DP83867_VQFN-48P_EP_A_A1: IC, DP83867, Single Port, Gigabit Ethernet PHY, VQFN-48; EN: 301-5-00106; KEY Number: 301-5-00106@1; Mfg: TEXAS INSTRUMENTS; Mfg Part No: DP83867CRRGZ*; Temperature: 0°C to +70°C
U53 U54 = IC_PUSB3F96_DFN-10P: IC, PUSB3F96, ESD Protection, UltraHigh-Speed Interfaces, DFN2510A-10; EN: 301-0-01093; KEY Number: 301-0-01093@1; Mfg: NXP SEMICONDUCTORS; Temperature: -40°C to +85°C
X3 = CRYSTAL_4P: XTAL, 25MHz, 18pF, +/-20ppm, 60E, 2.5x3.2mm, SMD; EN: 108-1-00057; KEY Number: 108-1-00057@1; Mfg: ABRACON CORPORATION; Mfg Part No: ABM8G-25.000MHZ-18-D2Y
FD1-FD6 = MECH_FID_G: Fiducial, Global, Pad=1mm, SM=3mm; EN: 666-1-00002; KEY Number: 666-1-00002@1; Mfg: NA; Mfg Part No: 666-1-00002
FD7-FD14 = MECH_FID_L: Fiducial, Local, Pad=1mm, SM=2mm; EN: 666-1-00001; KEY Number: 666-1-00001@1; Mfg: NA; Mfg Part No: 666-1-00001
MECH1-MECH4 = MECH_STANDOFF_A1: Mech, Solderable standoff, SS, M2x3.55; EN: 601-3-00725; KEY Number: 601-3-00725@1; Mfg: JAE (JAPAN AVIATION ELECTRONICS INDUSTRY, LTD); Temperature: NA
MH1-MH4 = MECH_MH_PL: MH, PTH, Pad=6mm, Via=3.2mm; EN: 666-1-00157; KEY Number: 666-1-00157@1; Mfg: NA; Mfg Part No: 666-1-00157; Temperature: NA

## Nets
GND: C117.2 C118.2 C119.2 C120.2 C121.2 C122.2 C123.2 C124.2 C125.2 C126.2 C127.2 C128.2 C129.2 C130.2 C131.2 C140.2 C141.2 C142.2 C143.2 C144.2 C145.2 C146.2 C147.2 C148.2 C149.2 C150.2 C151.2 C152.2 C153.2 C154.2 C155.2 C156.2 C157.2 C158.2 C159.2 C160.2 C161.2 C162.2 C163.2 C164.2 C165.2 C166.2 C167.2 C168.2 C169.2 C170.2 C171.2 C172.2 C173.2 C174.2 C175.2 C176.2 C177.2 C178.2 C179.2 C180.2 C199.2(CATHODE) C200.2 C201.2 C202.2(CATHODE) C203.2(CATHODE) C204.2(CATHODE) C249.2 C250.2 C251.2 C267.2 C268.2 C269.2 C270.2 C271.2 C272.2 C273.2 C280.2 C283.2 C284.2 C285.2 C286.2 C287.2 C288.2 C289.2 C290.2 C291.2 C292.2 C293.2 C294.2 C295.2 C296.2 C297.2 C302.2 C303.2 C304.2 C305.2 C306.2 C307.2 C308.2 C309.2 C310.2 C311.2 C362.2 C369.2 C370.2 C402.2 C403.2 C404.2 C405.2 C406.2 C407.2 C409.2 C410.2 C500.2 C503.2 C504.2 C507.2 C508.2 C509.2 C571.2 C576.2 D23.1(K1) D24.1(K1) D27.1(K1) D28.1(K1) D29.1(K1) D30.1(K1) J3.2(GND1) J3.3(GND2) J4.2(GND1) J4.3(GND2) J7.C5(GND) J8.4(GND1) J8.9(GND2) J8.15(GND3) J8.18(GND4) J8.21(GND5) J8.26(GND6) J8.27(GND7) J8.29(GND8) J8.34(GND9) J8.35(GND10) J8.37(GND11) J8.40(GND12) J8.43(GND13) J8.50(GND14) J8.S1 J8.S2 J15.1(SLEEVE) J27.10 J27.SH1 J27.SH2 MH1.1 MH2.1 MH3.1 MH4.1 R66.1 R67.1 R68.2 R70.1 R71.1 R75.1 R76.1 R80.1 R81.2 R82.1 R83.1 R84.1 R86.1 R116.2 R117.2 R118.2 R131.1 R155.2 R293.2 R297.2 R300.1 R303.2 R307.1 R308.1 R367.1 R449.2 R604.2 R606.2 R608.2 R634.1 R635.1 R660.1 R666.1 R667.1 R668.1 R669.2 R678.1 R679.2 R741.2 TP14.1 TP68.1 TP69.1 TP70.1 TP71.1 TP72.1 TP73.1 TP74.1 TP75.1 U7.AB1(ADC2_IN2) U7.AB2(ADC2_IN3) U7.AC1(ADC2_IN0) U7.AC2(ADC2_IN1) U7.AD1(ADC1_IN0) U7.AD3(ADC1_IN1) U7.AE2(ADC1_IN2) U7.AE3(ADC1_IN3) U8.A9(VSS1) U8.B1(VSSQ1) U8.B3(VSS2) U8.B9(VSSQ2) U8.D1(VSSQ3) U8.D8(VSSQ4) U8.E1(VSS3) U8.E2(VSSQ5) U8.E8(VSSQ6) U8.F9(VSSQ7) U8.G1(VSSQ8) U8.G8(VSS4) U8.G9(VSSQ9) U8.J2(VSS5) U8.J8(VSS6) U8.M1(VSS7) U8.M9(VSS8) U8.P1(VSS9) U8.P9(VSS10) U8.T1(VSS11) U8.T9(VSS12) U9.A9(VSS1) U9.B1(VSSQ1) U9.B3(VSS2) U9.B9(VSSQ2) U9.D1(VSSQ3) U9.D8(VSSQ4) U9.E1(VSS3) U9.E2(VSSQ5) U9.E8(VSSQ6) U9.F9(VSSQ7) U9.G1(VSSQ8) U9.G8(VSS4) U9.G9(VSSQ9) U9.J2(VSS5) U9.J8(VSS6) U9.M1(VSS7) U9.M9(VSS8) U9.P1(VSS9) U9.P9(VSS10) U9.T1(VSS11) U9.T9(VSS12) U13.49(GND_EP) U24.9(DGND) U24.20(SPKGND2) U24.24(SPKGND1) U24.28(AGND) U24.33(GND_EP) U42.5(GND_REFOUT) U42.6(GND_DIG) U42.10(GND1) U42.15(GNDA) U42.21(GND2) U42.24(GND_XTAL) U42.25(GND_EP) U53.3(GND1) U53.8(GND2) U54.3(GND1) U54.8(GND2) X3.2(GND1) X3.4(GND2) ; also on sheet 1 4 5 6 7 15 16 17 18 19 20 21
PVCC_I2C_SPI_UART_CAP: C128.1 U7.R9(PVCC_I2C_SPI_UART_CAP)
VDD_1V8: C124.1 C129.1 C406.1 C407.1 C409.1 C410.1 C509.1 FB3.1 FB4.1 FB19.2 R605.1 R607.1 U7.L9(NVCC_SPI) U42.3(VDD_OSC) U42.7(VDD_DIG) U42.11(VDDO1) U42.20(VDDO2) ; also on sheet 1 5 6 7 15 18 19
VDD_1V35: C142.1 C143.1 C144.1 C145.1 C146.1 C147.1 C148.1 C149.1 C150.1 C151.1 C152.1 C153.1 C154.1 C155.1 C156.1 C157.1 C158.1 C159.1 C160.1 C161.1 C162.1 C163.1 C164.1 C165.1 C166.1 C167.1 C168.1 C169.1 C170.1 C171.1 C172.1 C173.1 C174.1 C175.1 C176.1 C177.1 C178.1 C179.1 C180.1 R85.2 TP19.1 TP20.1 U7.AA16(NVCC_DRAM_06) U7.AA17(NVCC_DRAM_07) U7.AA18(NVCC_DRAM_08) U7.AA19(NVCC_DRAM_09) U7.AA20(NVCC_DRAM_10) U7.AA21(NVCC_DRAM_11) U7.T21(NVCC_DRAM_01) U7.U21(NVCC_DRAM_02) U7.V21(NVCC_DRAM_03) U7.W21(NVCC_DRAM_04) U7.Y21(NVCC_DRAM_05) U8.A1(VDDQ1) U8.A8(VDDQ2) U8.B2(VDD1) U8.C1(VDDQ3) U8.C9(VDDQ4) U8.D2(VDDQ5) U8.D9(VDD2) U8.E9(VDDQ6) U8.F1(VDDQ7) U8.G7(VDD3) U8.H2(VDDQ8) U8.H9(VDDQ9) U8.K2(VDD4) U8.K8(VDD5) U8.N1(VDD6) U8.N9(VDD7) U8.R1(VDD8) U8.R9(VDD9) U9.A1(VDDQ1) U9.A8(VDDQ2) U9.B2(VDD1) U9.C1(VDDQ3) U9.C9(VDDQ4) U9.D2(VDDQ5) U9.D9(VDD2) U9.E9(VDDQ6) U9.F1(VDDQ7) U9.G7(VDD3) U9.H2(VDDQ8) U9.H9(VDDQ9) U9.K2(VDD4) U9.K8(VDD5) U9.N1(VDD6) U9.N9(VDD7) U9.R1(VDD8) U9.R9(VDD9) ; also on sheet 1 5
VDD_3V3: C117.1 C118.1 C122.1 C127.1 C267.1 C268.1 FB21.2 FB41.1 R33.2 R34.2 R61.2 R62.2 R63.2 R64.2 R231.2 R235.2 U7.F9(VDD_USB_OTG2_3P3_IN) U7.F10(VDD_USB_OTG1_3P3_IN) U7.M8(NVCC_I2C) U7.N9(NVCC_UART) U24.8(DCVDD) U24.10(DBVDD) ; also on sheet 1 5 6 7 15 16 17 18 19 20 21
VDD_3V3_PERI: C199.1(ANODE) C200.1 C201.1 C202.1(ANODE) C203.1(ANODE) C204.1(ANODE) D5.1(A) D6.2(A) D7.2(A) J8.2(3P3VAUX) J8.24(3P3VAUX+_1) J8.39(3P3VAUX+_2) J8.41(3P3VAUX+_3) J8.52(3P3VAUX+_4) ; also on sheet 1 5
VDD_5V: FB40.1 ; also on sheet 5 16 17
VDD_HOST_VBUS: C123.1 R69.1 R71.2 U7.C10(USB_OTG2_VBUS)
VDD_LDO_1V5: C503.1 C504.1 J8.6(1V5) J8.28(1V5+_1) J8.48(1V5+_2) ; also on sheet 5
VDD_LDO_2V5: FB20.2 ; also on sheet 1
VDD_OTG1_1P0_CAP: C119.1 C120.1 U7.H10(VDD_USB_OTG1_1P0_CAP)
VDD_OTG2_1P0_CAP: C125.1 C126.1 U7.J11(VDD_USB_OTG2_1P0_CAP)
VDD_OTG_VBUS: C121.1 R65.1 R67.2 U7.C8(USB_OTG1_VBUS)
VDD_PHY_1V0: C251.1 C302.1 C303.1 C306.1 C307.1 C308.1 C309.1 C310.1 C311.1 C500.1 FB22.1 U13.6(VDD1P0[1]) U13.24(VDD1P0[2]) U13.31(VDD1P0[3]) U13.42(VDD1P0[4])
VDD_SOC_ARM: FB22.2 ; also on sheet 5 6
VDD_SPK: C269.1 C270.1 FB40.2 U24.21(SPKVDD2) U24.26(SPKVDD1)
VDDA_ADC_1P8: C130.1 C131.1 C362.1 FB3.2 U7.AB3(VDDA_ADC2_1P8) U7.AC3(VDDA_ADC1_1P8) U7.AC4(VDD_TEMPSENSOR_1P8)
VDDA_CLKGEN_1V8: C404.1 C405.1 FB4.2 U42.16(VDDA)
VDDA_PHY_1V8: C280.1 C283.1 C284.1 C285.1 C507.1 C508.1 FB19.1 U13.13(VDDA1P8[1]) U13.48(VDDA1P8[2])
VDDA_PHY_2V5: C286.1 C287.1 C288.1 C289.1 C290.1 C291.1 FB20.1 U13.3(VDDA2P5[1]) U13.9(VDDA2P5[2])
VDDIO_PHY_3V3: C249.1 C250.1 C292.1 C293.1 C294.1 C295.1 C296.1 C297.1 FB21.1 R129.1 R301.2 R302.2 R306.2 R663.2 R664.2 R665.2 R688.2 U13.19(VDDIO1) U13.30(VDDIO2) U13.41(VDDIO3)
ALS_I2C_SCL: R242.1 ; also on sheet 17
ALS_I2C_SDA: R247.1 ; also on sheet 17
AUD_3V3: C271.1 FB41.2 R366.1 U24.32(AVDD)
AUD_I2C_SCL: R515.1 U24.17(SCLK)
AUD_I2C_SDA: R520.1 U24.18(SDIN)
AUDIO_MCLK: U24.11(MCLK) ; also on sheet 7
AUDIO_RXD: U24.16(ADCDAT) ; also on sheet 7
AUDIO_TXC: U24.12(BCLK) ; also on sheet 7
AUDIO_TXD: U24.14(DACDAT) ; also on sheet 7
AUDIO_TXFS: U24.13(DACLRC) ; also on sheet 7
BT_REG_ON: U7.J6(ECSPI2_SS0) ; also on sheet 15
CAN2_RX: U7.T5(GPIO1_IO14) ; also on sheet 17
CAN2_TX: U7.T6(GPIO1_IO15) ; also on sheet 17
CLKGEN_OE0_B: R155.1 U42.12(OE0#)
CLKGEN_OE1_B: R449.1 U42.19(OE1#)
CLKGEN_Q0_N: R598.1 U42.14(Q0-)
CLKGEN_Q0_P: R597.1 U42.13(Q0+)
CLKGEN_Q1_N: R633.1 U42.18(Q1-)
CLKGEN_Q1_P: R632.1 U42.17(Q1+)
CLKGEN_XIN: C402.1 U42.1(XTAL_IN/CLK) X4.1
CLKGEN_XOUT: C403.1 U42.2(XTAL_OUT) X4.2
Codec_GPIO_INT: U24.15(ADCLRC/GPIO1) ; also on sheet 7
CSENS1_I2C_SCL: R723.1 ; also on sheet 5
CSENS1_I2C_SDA: R724.1 ; also on sheet 5
CSENS2_I2C_SCL: R726.1 ; also on sheet 5
CSENS2_I2C_SDA: R725.1 ; also on sheet 5
CSI_I2C_SCL: R516.1 ; also on sheet 19
CSI_I2C_SDA: R521.1 ; also on sheet 19
DDR_SDCLK0_N: R618.1 U7.AD25(DRAM_SDCLK0_N)
DDR_SDCLK0_P: R617.1 U7.AD24(DRAM_SDCLK0_P)
DDR_VREF: C141.1 U7.AC13(DRAM_VREF) U8.H1(VREFDQ) U8.M8(VREFCA) U9.H1(VREFDQ) U9.M8(VREFCA) ; also on sheet 1
DRAM0_ZQ: R83.2 U8.L8(ZQ)
DRAM0_ZQ1: R81.1 U8.L9(NC)
DRAM1_ZQ: R84.2 U9.L8(ZQ)
DRAM1_ZQ1: R82.2 U9.L9(NC)
DRAM_ADDR0: U7.AB19(DRAM_ADDR00) U8.N3(A0) U9.N3(A0)
DRAM_ADDR1: U7.AB16(DRAM_ADDR01) U8.P7(A1) U9.P7(A1)
DRAM_ADDR2: U7.AC18(DRAM_ADDR02) U8.P3(A2) U9.P3(A2)
DRAM_ADDR3: U7.AC20(DRAM_ADDR03) U8.N2(A3) U9.N2(A3)
DRAM_ADDR4: U7.AB21(DRAM_ADDR04) U8.P8(A4) U9.P8(A4)
DRAM_ADDR5: U7.Y23(DRAM_ADDR05) U8.P2(A5) U9.P2(A5)
DRAM_ADDR6: U7.V22(DRAM_ADDR06) U8.R8(A6) U9.R8(A6)
DRAM_ADDR7: U7.Y22(DRAM_ADDR07) U8.R2(A7) U9.R2(A7)
DRAM_ADDR8: U7.W22(DRAM_ADDR08) U8.T8(A8) U9.T8(A8)
DRAM_ADDR9: U7.V23(DRAM_ADDR09) U8.R3(A9) U9.R3(A9)
DRAM_ADDR10: U7.T23(DRAM_ADDR10) U8.L7(A10/AP) U9.L7(A10/AP)
DRAM_ADDR11: U7.U22(DRAM_ADDR11) U8.R7(A11) U9.R7(A11)
DRAM_ADDR12: U7.T22(DRAM_ADDR12) U8.N7(A12/~{BC}) U9.N7(A12/~{BC})
DRAM_ADDR13: U7.P23(DRAM_ADDR13) U8.T3(A13) U9.T3(A13)
DRAM_ADDR14: U7.AB18(DRAM_ADDR14) U8.T7(A14) U9.T7(A14)
DRAM_ADDR15: U7.AB20(DRAM_ADDR15) U8.M7(NC) U9.M7(NC)
DRAM_CAS_B: U7.AC14(~{DRAM_CAS}) U8.K3(~{CAS}) U9.K3(~{CAS})
DRAM_CS0_B: U7.AB23(~{DRAM_CS0}) U8.L2(~{CS}) U9.L2(~{CS})
DRAM_CS1_B: U7.AA22(~{DRAM_CS1}) U8.L1(NC) U9.L1(NC)
DRAM_DATA0: U7.AD22(DRAM_DATA00) U8.D7(DQ8)
DRAM_DATA1: U7.AD23(DRAM_DATA01) U8.C8(DQ10)
DRAM_DATA2: U7.AE20(DRAM_DATA02) U8.C3(DQ9)
DRAM_DATA3: U7.AE23(DRAM_DATA03) U8.B8(DQ14)
DRAM_DATA4: U7.AE22(DRAM_DATA04) U8.A7(DQ12)
DRAM_DATA5: U7.AD19(DRAM_DATA05) U8.A3(DQ15)
DRAM_DATA6: TP15.1 TP16.1 U7.AD18(DRAM_DATA06) U8.A2(DQ13)
DRAM_DATA7: U7.AE19(DRAM_DATA07) U8.C2(DQ11)
DRAM_DATA8: U7.AE14(DRAM_DATA08) U8.E3(DQ0)
DRAM_DATA9: U7.AE18(DRAM_DATA09) U8.H8(DQ5)
DRAM_DATA10: U7.AE17(DRAM_DATA10) U8.F8(DQ3)
DRAM_DATA11: U7.AD16(DRAM_DATA11) U8.H7(DQ7)
DRAM_DATA12: U7.AE16(DRAM_DATA12) U8.F7(DQ1)
DRAM_DATA13: U7.AD14(DRAM_DATA13) U8.H3(DQ4)
DRAM_DATA14: U7.AD13(DRAM_DATA14) U8.G2(DQ6)
DRAM_DATA15: U7.AE13(DRAM_DATA15) U8.F2(DQ2)
DRAM_DATA16: U7.AA25(DRAM_DATA16) U9.D7(DQ8)
DRAM_DATA17: U7.W24(DRAM_DATA17) U9.C8(DQ10)
DRAM_DATA18: TP17.1 TP18.1 U7.V25(DRAM_DATA18) U9.B8(DQ14)
DRAM_DATA19: U7.W25(DRAM_DATA19) U9.A7(DQ12)
DRAM_DATA20: U7.AC25(DRAM_DATA20) U9.A2(DQ13)
DRAM_DATA21: U7.AB25(DRAM_DATA21) U9.C3(DQ9)
DRAM_DATA22: U7.AB24(DRAM_DATA22) U9.A3(DQ15)
DRAM_DATA23: U7.AC24(DRAM_DATA23) U9.C2(DQ11)
DRAM_DATA24: U7.R25(DRAM_DATA24) U9.E3(DQ0)
DRAM_DATA25: U7.N24(DRAM_DATA25) U9.H8(DQ5)
DRAM_DATA26: U7.P25(DRAM_DATA26) U9.H7(DQ7)
DRAM_DATA27: U7.N25(DRAM_DATA27) U9.F8(DQ3)
DRAM_DATA28: U7.U25(DRAM_DATA28) U9.G2(DQ6)
DRAM_DATA29: U7.R24(DRAM_DATA29) U9.F7(DQ1)
DRAM_DATA30: U7.U24(DRAM_DATA30) U9.H3(DQ4)
DRAM_DATA31: U7.V24(DRAM_DATA31) U9.F2(DQ2)
DRAM_DQM0: U7.AD20(DRAM_DQM0) U8.D3(UDM)
DRAM_DQM1: U7.AD17(DRAM_DQM1) U8.E7(LDM)
DRAM_DQM2: U7.AA24(DRAM_DQM2) U9.D3(UDM)
DRAM_DQM3: U7.P24(DRAM_DQM3) U9.E7(LDM)
DRAM_ODT0: U7.AC16(DRAM_ODT0) U8.K1(ODT) U9.K1(ODT)
DRAM_ODT1: U7.AA14(DRAM_ODT1) U8.J1(NC) U9.J1(NC)
DRAM_RAS_B: U7.AB15(~{DRAM_RAS}) U8.J3(~{RAS}) U9.J3(~{RAS})
DRAM_RESET: R116.1 U7.AC22(DRAM_RESET) U8.T2(~{RESET}) U9.T2(~{RESET})
DRAM_SDBA0: U7.R22(DRAM_SDBA0) U8.M2(BA0) U9.M2(BA0)
DRAM_SDBA1: U7.P22(DRAM_SDBA1) U8.N8(BA1) U9.N8(BA1)
DRAM_SDBA2: U7.N23(DRAM_SDBA2) U8.M3(BA2) U9.M3(BA2)
DRAM_SDCKE0: R118.1 U7.AB17(DRAM_SDCKE0) U8.K9(CKE) U9.K9(CKE)
DRAM_SDCKE1: R117.1 U7.AB22(DRAM_SDCKE1) U8.J9(NC) U9.J9(NC)
DRAM_SDCLK0_N: R90.2 R91.2 R618.2 TP23.1 TP24.1 U8.K7(~{CK}) U9.K7(~{CK})
DRAM_SDCLK0_P: R90.1 R91.1 R617.2 TP21.1 TP22.1 U8.J7(CK) U9.J7(CK)
DRAM_SDQS0_N: TP41.1 TP42.1 U7.AD21(DRAM_SDQS0_N) U8.B7(~{UDQS})
DRAM_SDQS0_P: TP40.1 TP43.1 U7.AE21(DRAM_SDQS0_P) U8.C7(UDQS)
DRAM_SDQS1_N: U7.AE15(DRAM_SDQS1_N) U8.G3(~{LDQS})
DRAM_SDQS1_P: U7.AD15(DRAM_SDQS1_P) U8.F3(LDQS)
DRAM_SDQS2_N: TP44.1 TP46.1 U7.Y25(DRAM_SDQS2_N) U9.B7(~{UDQS})
DRAM_SDQS2_P: TP45.1 TP47.1 U7.Y24(DRAM_SDQS2_P) U9.C7(UDQS)
DRAM_SDQS3_N: U7.T25(DRAM_SDQS3_N) U9.G3(~{LDQS})
DRAM_SDQS3_P: U7.T24(DRAM_SDQS3_P) U9.F3(LDQS)
DRAM_SDWE_B: U7.AB14(~{DRAM_SDWE}) U8.L3(~{WE}) U9.L3(~{WE})
DRAM_ZQ: R86.2 U7.AB13(DRAM_ZQPAD)
EEPROM_I2C1_SCL: R233.1 ; also on sheet 7
EEPROM_I2C1_SDA: R237.1 ; also on sheet 7
ENET_INT_B: R680.2 R688.1 U7.M1(UART3_RXD)
ENET_MDC: R95.1 U13.16(MDC)
ENET_MDIO: R129.2 U7.R5(GPIO1_IO10) U13.17(MDIO)
ENET_RST_B: R131.2 U7.R2(GPIO1_IO09) U13.43(RESET#)
FB_HPOUTL: D23.2(K2) FB11.2 J15.2(TIP) R367.2
FB_HPOUTR: D24.2(K2) FB12.2 J15.3(RING)
GWDOG_RST_B: U7.N1(GPIO1_IO00) ; also on sheet 19
HP_DETEC: J15.4(TIP_SWITCH) R366.2 U24.2(LINPUT3/JD2)
HP_L: C274.1(ANODE) U24.31(HP_L)
HP_R: C275.1(ANODE) U24.29(HP_R)
HPOUTL: C274.2(CATHODE) C369.1 FB11.1
HPOUTR: C275.2(CATHODE) C370.1 FB12.1
HSIC_DATA: J4.1(SIG) U7.A12(USB_H_DATA)
HSIC_STROBE: J3.1(SIG) U7.B12(USB_H_STROBE)
I2C1_SCL: R231.1 R232.1 R233.2 R234.1 U7.J2(I2C1_SCL)
I2C1_SDA: R235.1 R236.1 R237.2 R238.2 U7.K1(I2C1_SDA)
I2C2_SCL: R61.1 R242.2 R506.2 U7.K2(I2C2_SCL)
I2C2_SDA: R62.1 R247.2 R504.2 U7.K3(I2C2_SDA)
I2C3_SCL: R63.1 R508.2 R723.2 R726.2 U7.K5(I2C3_SCL)
I2C3_SDA: R64.1 R509.2 R724.2 R725.2 U7.K6(I2C3_SDA)
I2C4_SCL: R33.1 R515.2 R516.2 R595.2 ; also on sheet 7
I2C4_SDA: R34.1 R520.2 R521.2 R596.2 ; also on sheet 7
LCD1_PWM: U7.N2(GPIO1_IO01) ; also on sheet 17
LCD_I2C_SCL: R508.1 ; also on sheet 17
LCD_I2C_SDA: R509.1 ; also on sheet 17
LD_WLAN_B: D6.1(K) R146.1
LD_WPAN_B: D7.1(K) R147.1
LD_WWAN_B: D5.2(K) R145.1
LED_WLAN_B: J8.44(LED_WLAN#) R146.2
LED_WPAN_B: J8.46(LED_WPAN#) R147.2
LED_WWAN_B: J8.42(LED_WWAN#) R145.2
LIN1: C260.1 U24.4(LINPUT1)
LIN2: C318.1 U24.3(LINPUT2)
MIC_N: MK1.2(NEG) R678.2 R679.1 R684.2
MIC_P: C318.2 MK1.1(POS) R182.2
MICBIAS: C272.1 R182.1 U24.1(MICBIAS)
MIPI_CSI_CLK_N: U7.A15(MIPI_CSI_CLK_N) ; also on sheet 19
MIPI_CSI_CLK_P: U7.B15(MIPI_CSI_CLK_P) ; also on sheet 19
MIPI_CSI_D0_N: U7.A16(MIPI_CSI_D0_N) ; also on sheet 19
MIPI_CSI_D0_P: U7.B16(MIPI_CSI_D0_P) ; also on sheet 19
MIPI_CSI_D1_N: U7.A14(MIPI_CSI_D1_N) ; also on sheet 19
MIPI_CSI_D1_P: U7.B14(MIPI_CSI_D1_P) ; also on sheet 19
NVCC_DRAM_CKE: C140.1 R85.1 U7.Y20(NVCC_DRAM_CKE)
OTG1_CHD_B: TP48.1 U7.C7(~{USB_OTG1_CHD})
OTG1_REXT: R66.2 U7.A7(USB_OTG1_REXT)
OTG2_REXT: R70.2 U7.A11(USB_OTG2_REXT)
OUT3: C276.1 U24.30(OUT3)
PCIE_CLK_GEN_SCL: R595.1 U42.8(SCLK)
PCIE_CLK_GEN_SDA: R596.1 U42.9(SDATA)
PCIE_CLKGEN_SS_SEL: R604.1 U42.23(SS_SEL_TRI)
PCIe_CTXM: C207.2 J8.31(PETN0)
PCIe_CTXP: C208.2 J8.33(PETP0)
PCIE_DIS_B: J8.20(W_DISABLE#) U7.T2(GPIO1_IO12)
PCIE_REFCLK_N: R607.2 R608.1 R633.2 U7.AE10(PCIE_REFCLKIN_N)
PCIE_REFCLK_P: R605.2 R606.1 R632.2 U7.AD10(PCIE_REFCLKIN_P)
PCIE_REFCLKOUT_N: R598.2 R645.1 U7.AC10(PCIE_REFCLKOUT_N)
PCIE_REFCLKOUT_N0: J8.11(REFCLK-) R634.2 R645.2
PCIE_REFCLKOUT_P: R597.2 R644.1 U7.AB10(PCIE_REFCLKOUT_P)
PCIE_REFCLKOUT_P0: J8.13(REFCLK+) R635.2 R644.2
PCIe_REXT: R80.2 U7.AA13(PCIE_REXT)
PCIE_RST_B: J8.22(PERST#) U7.T3(GPIO1_IO13)
PCIE_RX_N: R96.1 U7.AE11(PCIE_RX_N)
PCIE_RX_P: R97.1 U7.AD11(PCIE_RX_P)
PCIe_RXN_R: J8.23(PERN0) R96.2
PCIe_RXP_R: J8.25(PERP0) R97.2
PCIe_SMB_CLK: J8.30(SMB_CLK) R506.1
PCIe_SMB_DATA: J8.32(SMB_DATA) R504.1
PCIE_TX_N: C207.1 U7.AC11(PCIE_TX_N)
PCIE_TX_P: C208.1 U7.AB11(PCIE_TX_P)
PCIe_UIM_CLK: J7.C3(CLK) J8.12(UIM_CLK)
PCIe_UIM_DATA: J7.C7(I/O) J8.10(UIM_DATA)
PCIe_UIM_PWR: C571.1 J7.C1(VCC) J8.8(UIM_PWR)
PCIe_UIM_RST: J7.C2(RESET) J8.14(UIM_RESET)
PCIe_UIM_VPP: J7.C6(VPP) J8.16(UIM_VPP)
PCIE_USB_DM: FL3.4 J8.36(USB_D-)
PCIE_USB_DP: FL3.1 J8.38(USB_D+)
PHY_CLKOUT: TP62.1 U13.18(CLK_OUT)
PHY_CT: C576.1 J27.1
PHY_GPIO0: R664.1 R666.2 U13.39(GPIO_0)
PHY_GPIO1: R665.1 R667.2 U13.40(GPIO_1)
PHY_INT_B: R680.1 U13.44(INT#/PWDN#)
PHY_JTAG: R741.1 U13.20(JTAG_CLK) U13.22(JTAG_TMS) U13.23(JTAG_TDI)
PHY_LED0: D14.2(A) R663.1 R668.2 U13.47(LED_0)
PHY_LED1: J27.13(GA2/YK2) R301.1 R307.2 U13.46(LED_1)
PHY_LED2: J27.12(GK1/YA1) R302.1 R308.2 U13.45(LED_2)
PHY_MDI_A_M: J27.3 U13.2(TD_M_A) U53.2(CH2) U53.9(NC3)
PHY_MDI_A_P: J27.2 U13.1(TD_P_A) U53.1(CH1) U53.10(NC4)
PHY_MDI_B_M: J27.5 U13.5(TD_M_B) U53.5(CH4) U53.6(NC1)
PHY_MDI_B_P: J27.4 U13.4(TD_P_B) U53.4(CH3) U53.7(NC2)
PHY_MDI_C_M: J27.7 U13.8(TD_M_C) U54.2(CH2) U54.9(NC3)
PHY_MDI_C_P: J27.6 U13.7(TD_P_C) U54.1(CH1) U54.10(NC4)
PHY_MDI_D_M: J27.9 U13.11(TD_M_D) U54.5(CH4) U54.6(NC1)
PHY_MDI_D_P: J27.8 U13.10(TD_P_D) U54.4(CH3) U54.7(NC2)
PHY_RBIAS: R669.1 U13.12(RBIAS)
PHY_XI: C305.1 U13.15(XI) X3.1
PHY_XO: C304.1 R130.2 X3.3
PMIC_I2C1_SCL: R232.2 ; also on sheet 5
PMIC_I2C1_SDA: R236.2 ; also on sheet 5
PMIC_INT_B: U7.N5(GPIO1_IO03) ; also on sheet 5
PMIC_PFO_B: U7.N3(GPIO1_IO02) ; also on sheet 5
PMIC_SD_VSEL: U7.R1(GPIO1_IO08) ; also on sheet 1
RES_PHY_LED0: D14.1(K) R293.1
RES_PHY_LED1: J27.14(GK2/YA2) R303.1
RES_PHY_LED2: J27.11(GA1/YK1) R297.1
RGMII1_RX_CTL: R283.2 ; also on sheet 7
RGMII1_RXC: R282.2 ; also on sheet 7
RGMII1_RXD0: R278.2 ; also on sheet 7
RGMII1_RXD1: R279.2 ; also on sheet 7
RGMII1_RXD2: R280.2 ; also on sheet 7
RGMII1_RXD3: R281.2 ; also on sheet 7
RGMII1_TX_CTL: U13.37(TX_CTRL) ; also on sheet 7
RGMII1_TXC: U13.29(GTX_CLK) ; also on sheet 7
RGMII1_TXD0: U13.28(TX_D0) ; also on sheet 7
RGMII1_TXD1: U13.27(TX_D1) ; also on sheet 7
RGMII1_TXD2: U13.26(TX_D2) ; also on sheet 7
RGMII1_TXD3: U13.25(TX_D3) ; also on sheet 7
RX_CLK: R282.1 U13.32(RX_CLK)
RX_CTRL: R283.1 R300.2 R306.1 U13.38(RX_CTRL)
RX_D0: R278.1 U13.33(RX_D0)
RX_D1: R279.1 U13.34(RX_D1)
RX_D2: R280.1 U13.35(RX_D2)
RX_D3: R281.1 U13.36(RX_D3)
SOC_OTG2_DN: R559.1 R566.1 U7.A10(USB_OTG2_DN)
SOC_OTG2_DP: R558.1 R565.1 U7.B10(USB_OTG2_DP)
SPKLN: D28.2(K2) FB17.2 H3.2
SPKLP: D27.2(K2) FB14.2 H3.1
SPKOUTLN: FB17.1 U24.23(SPK_LN)
SPKOUTLP: FB14.1 U24.25(SPK_LP)
SPKOUTRN: FB16.1 U24.19(SPK_RN)
SPKOUTRP: FB13.1 U24.22(SPK_RP)
SPKRN: D30.2(K2) FB16.2 H3.4
SPKRP: D29.2(K2) FB13.2 H3.3
ST_ENET_MDC: R95.2 U7.T1(GPIO1_IO11)
ST_MIC_N: C260.2 R660.2 R684.1
ST_PHY_XO: R130.1 U13.14(XO)
TEMP_SENSOR_REXT: R75.2 U7.AE4(TEMPSENSOR_REXT)
TMPSEN_RESERV: R76.2 U7.AD4(TEMPSENSOR_RESERVE)
TP_OUT3: C276.2 TP29.1
UART1_RXD: U7.L3(UART1_RXD) ; also on sheet 20
UART1_TXD: U7.L4(UART1_TXD) ; also on sheet 20
UART2_RXD: U7.L5(UART2_RXD) ; also on sheet 20
UART2_TXD: U7.L6(UART2_TXD) ; also on sheet 20
UART5_RX: U7.L1(I2C4_SCL) ; also on sheet 21
UART5_TX: U7.L2(I2C4_SDA) ; also on sheet 21
UART6_CTS_B: U7.H5(ECSPI1_SS0) ; also on sheet 15
UART6_RTS_B: U7.H4(ECSPI1_MISO) ; also on sheet 15
UART6_RXD: U7.H3(ECSPI1_SCLK) ; also on sheet 15
UART6_TXD: U7.G5(ECSPI1_MOSI) ; also on sheet 15
USB2ANY_I2C1_SCL: R234.2 ; also on sheet 5
USB2ANY_I2C1_SDA: R238.1 ; also on sheet 5
USB_HOST_VBUS: R69.2 R569.2 ; also on sheet 16
USB_OTG1_DN: U7.A8(USB_OTG1_DN) ; also on sheet 16
USB_OTG1_DP: U7.B8(USB_OTG1_DP) ; also on sheet 16
USB_OTG1_ID: U7.B7(USB_OTG1_ID) ; also on sheet 16
USB_OTG1_OC: U7.N6(GPIO1_IO04) ; also on sheet 16
USB_OTG1_PWR: U7.P1(GPIO1_IO05) ; also on sheet 16
USB_OTG2_DN: R566.2 ; also on sheet 16
USB_OTG2_DP: R565.2 ; also on sheet 16
USB_OTG2_ID: R68.1 U7.B11(USB_OTG2_ID)
USB_OTG2_OC: U7.P2(GPIO1_IO06) ; also on sheet 16
USB_OTG2_PWR: U7.P3(GPIO1_IO07) ; also on sheet 16
USB_OTG_VBUS: R65.2 R569.1 ; also on sheet 16
USB_PCIE_DN: FL3.3 R559.2
USB_PCIE_DP: FL3.2 R558.2
VMIDC: C273.1 U24.27(VMID)
WL_IRQ: U7.H6(ECSPI2_MISO) ; also on sheet 15
WL_REG_ON: U7.G6(ECSPI2_MOSI) ; also on sheet 15

Not connected (* = marked no-connect by the designer): FD1 1*; FD2 1*; FD3 1*; FD4 1*; FD5 1*; FD6 1*; FD7 1*; FD8 1*; FD9 1*; FD10 1*; FD11 1*; FD12 1*; FD13 1*; FD14 1*; J7 C4(RSVD1)* C8(RSVD2)*; J8 1(WAKE#)* 3(COEX1)* 5(COEX2)* 7(CLKREQ#)* 17(UIM_C8)* 19(UIM_C4)* 45(RESERVED1)* 47(RESERVED2)* 49(RESERVED3)* 51(RESERVED4)*; MECH1 1*; MECH2 1*; MECH3 1*; MECH4 1*; U7 A18(MIPI_DSI_D1_N)* A19(MIPI_DSI_CLK_N)* A20(MIPI_DSI_D0_N)* B18(MIPI_DSI_D1_P)* B19(MIPI_DSI_CLK_P)* B20(MIPI_DSI_D0_P)* J5(ECSPI2_SCLK)* M2(UART3_TXD)* M5(UART3_RTS)* M6(UART3_CTS)*; U13 21(JTAG_TDO)*; U24 5(RINPUT1)* 6(RINPUT2)* 7(RINPUT3/JD3)*; U42 4(SADR/REFOUT)* 22(PD#)*

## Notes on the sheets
sheet 8
- CPU SIGNAL 2
- PMIC/EEPROM
- ALS/PCIe
- Use 90 ohm trace for USB differential pairs
- LCD/Current Sense 1&2
- WIFI/BT
- Cortex-A7
- Cortex-M4
- Use 50 ohm trace
- Use 100 ohm trace for MIPI differential pairs
- WDOG
  LCD
- USB
- Layout: Place R95
  as close to Processor
- ENET
- Mini PCIe
- CAN
- Analog Section Unused,
  so tied to ground
- Layout: PCIE REF Clock Route 100ohm DIFF
- Layout: PCIE Signal Route 85ohm DIFF
sheet 9
- DDR3L
- DRAM1
- DRAM0
- Clock terminators: Place termination resistor
   on each of the chip of CLK signals
- GND probe pads
- CAP for CPU
- Note: test points for signal integrity measurement
- Place near the  i.MX7D side
- Place near the  DDR3L side
- CAP for DRAM0
- CAP for DRAM1
- TEST POINT--GND
sheet 10
- Mini-PCIE
- Place R634, R635 near mini PCIe
- Layout: 100 ohm differential pair for REFCLK
  Layout: 85 ohm differential pairs for PCIE_TX/RX
- Layout:Place C207and C208 close to the mPCIe connector.
- Layout: USB 90 ohm differential pairs
- NOTE:
  This design assumes a normal loading on the VDD_3V3_PERI rail of up to 1A.
  The VDD_LDO_1V5 rail is allowed a maximum of 250 mA.
- I2C Addr: 0x68
sheet 11
- AUDIO
- HP OUT
- Keep ESD Diodes near Headphone connector
- Speaker Out
- MIC INPUT
- Keep ESD Diodes near SPK connector
sheet 12
- I2C1
- I2C2
- I2C3
- I2C4
sheet 13
- ETHERNET PHY
- Layout: Place 1uF, 0.1uF capacitor as
  close as possible to VDD pins
- Layout: Place 49E9 Resistors in
  RX_D[0:3], RX_CLK, RX_CTRL as close
  to PHY
- PHY address set to 0X00
- The RESET input must be held low
  for a minimum of 1µs
- Mirror Enable=[0]
  For Enabling Mount R869, R870
- RGMII Clock Skew RX[0:2]=[000]
- Autoneg enable. For Disabling
  R306=2.49K, R300=NM
- RGMII Clock Skew TX[0:2]=[000]
  ANEG_SEL(Auto-negotiation)=[0]
  PHY_LED[0:2] CANT CONFIGURE IN MODE4
- All path length from P2, P3 should  be kept
  small to minimize parasitic inductance. Also
  place near the connector J27
sheet 14
- MISCELLANEOUS
- MOUNTING HOLES
- GLOBAL FIDUCIALS
- LOCAL FIDUCIALS
- MINI PCIe HANDOFF
